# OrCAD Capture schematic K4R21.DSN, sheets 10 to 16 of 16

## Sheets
10 P11: Power, DDR3/VTT/VCore: size Custom; title: System Power supplies
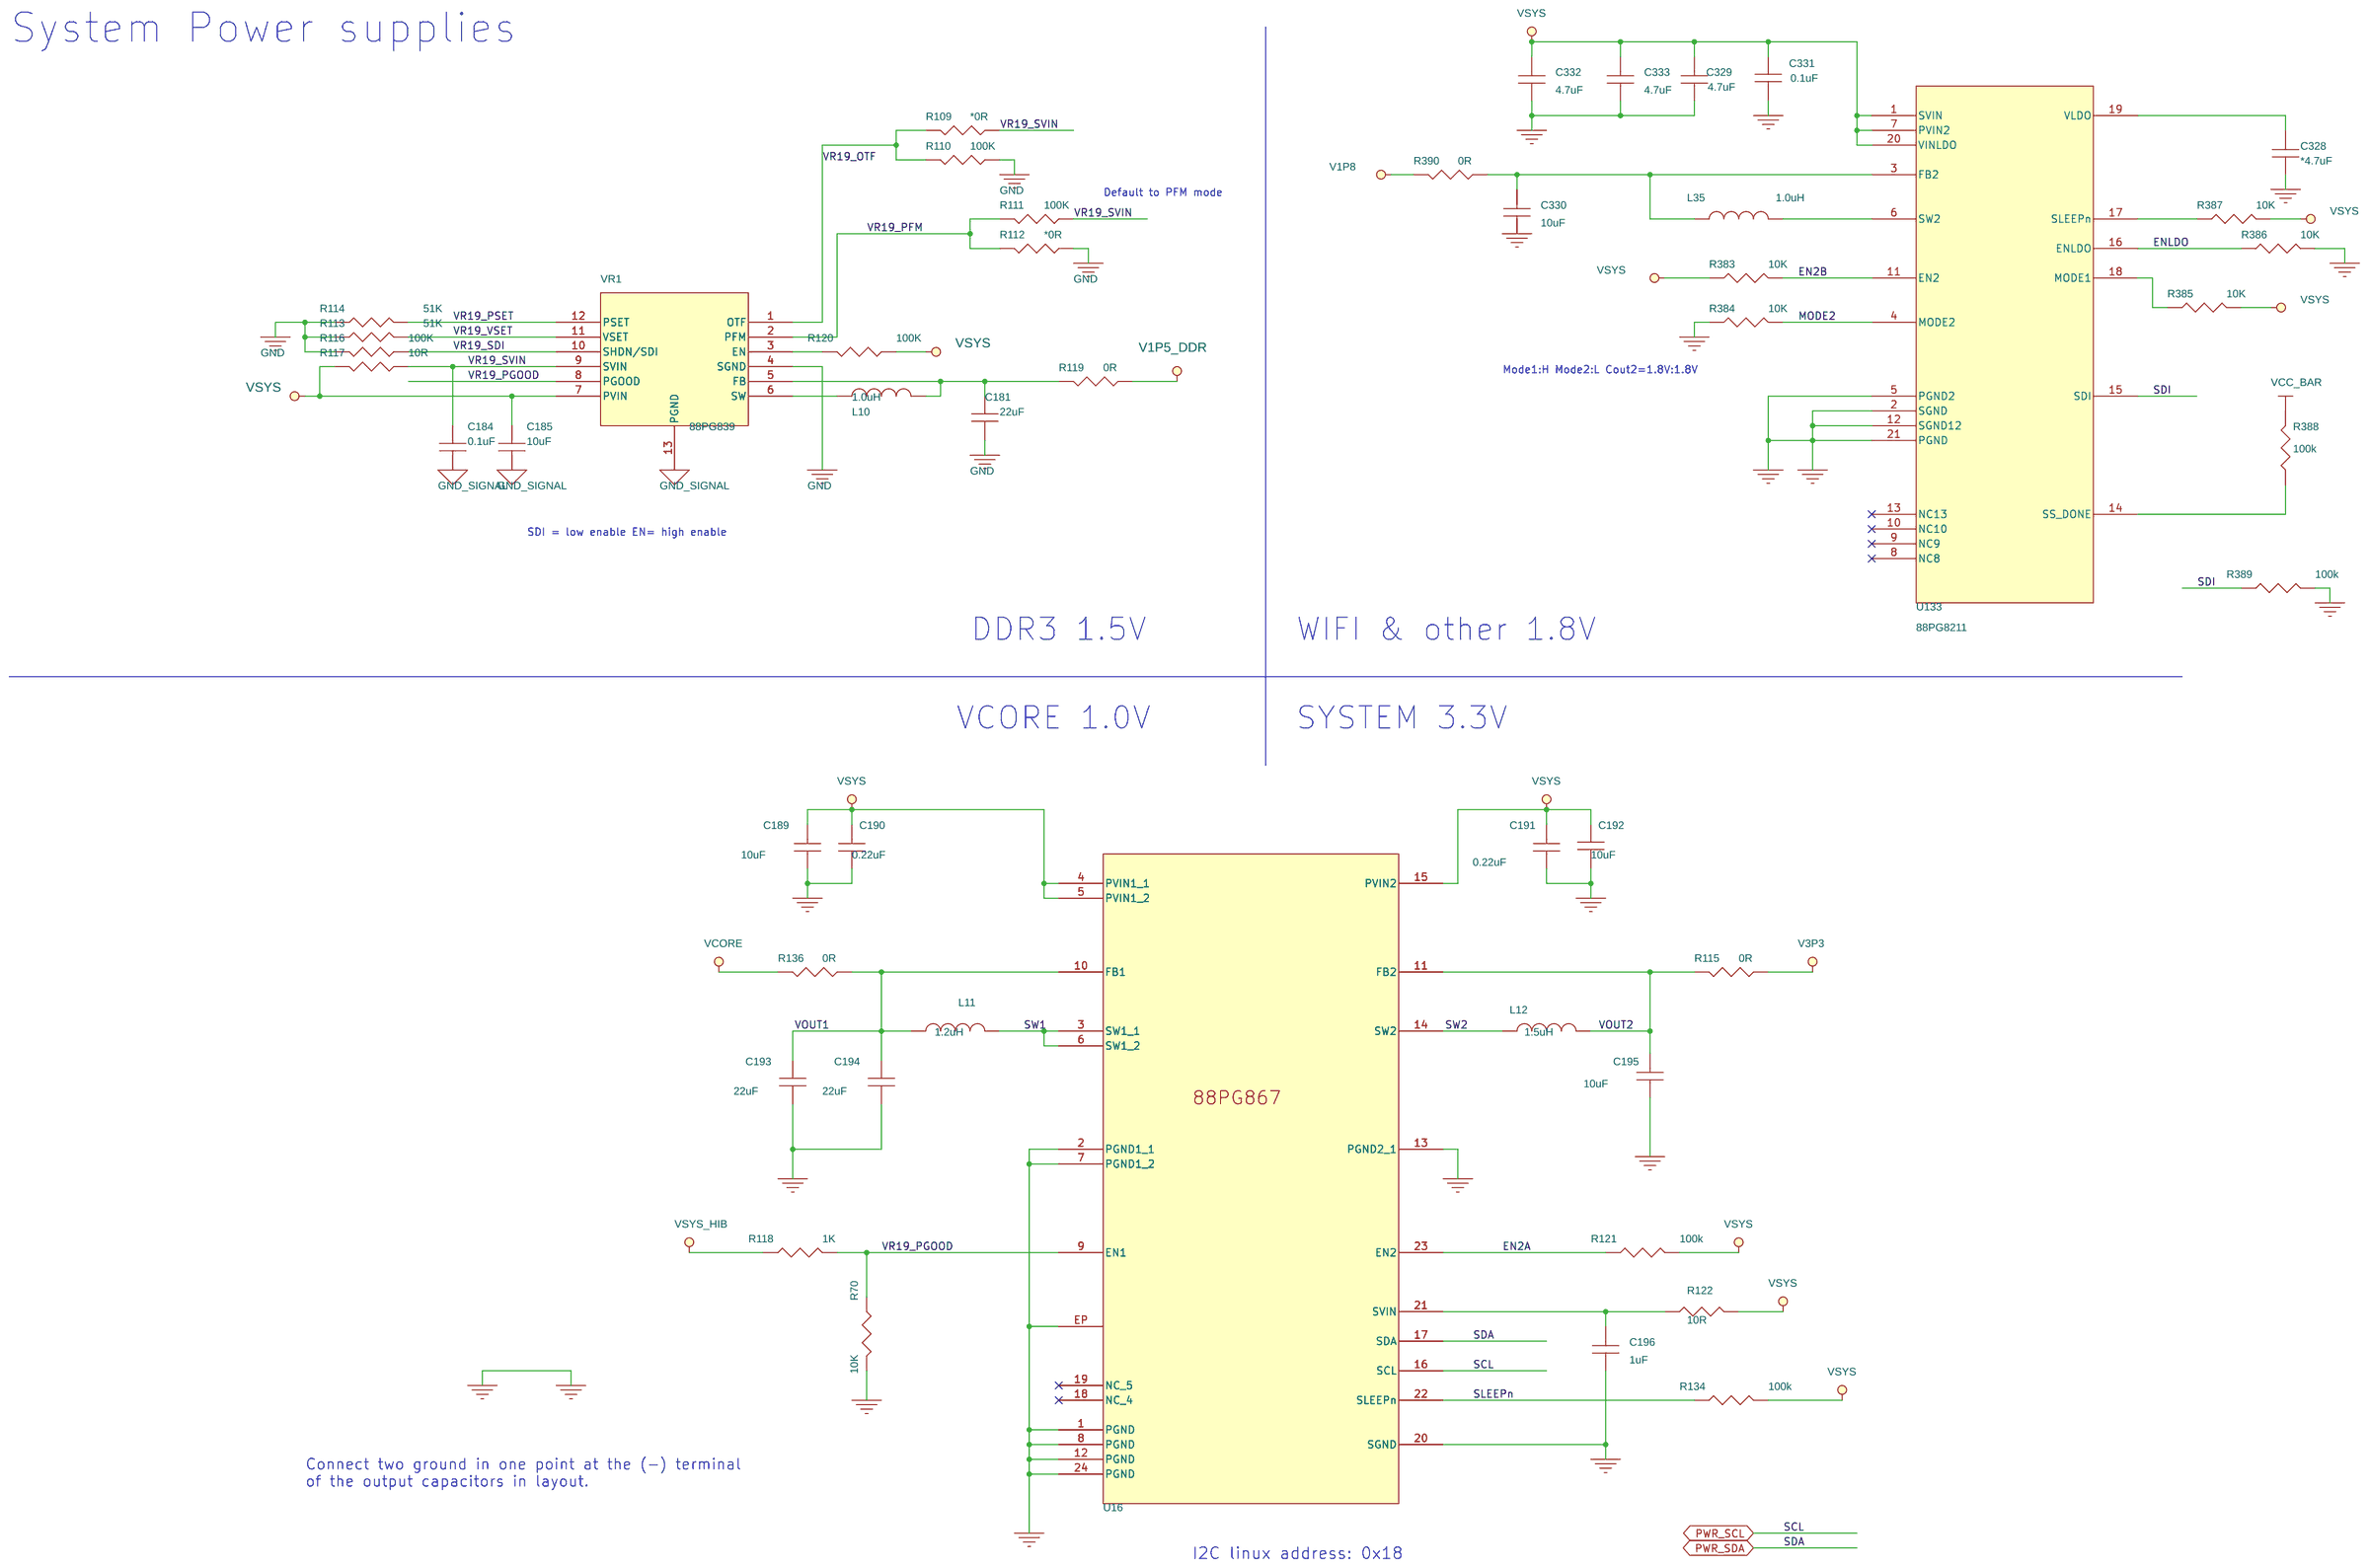
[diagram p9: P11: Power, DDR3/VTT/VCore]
11 P03: ASPEN-AUDIO/SDIO/MISC: size Custom; title: ASPEN-SPI/SDIO/etc
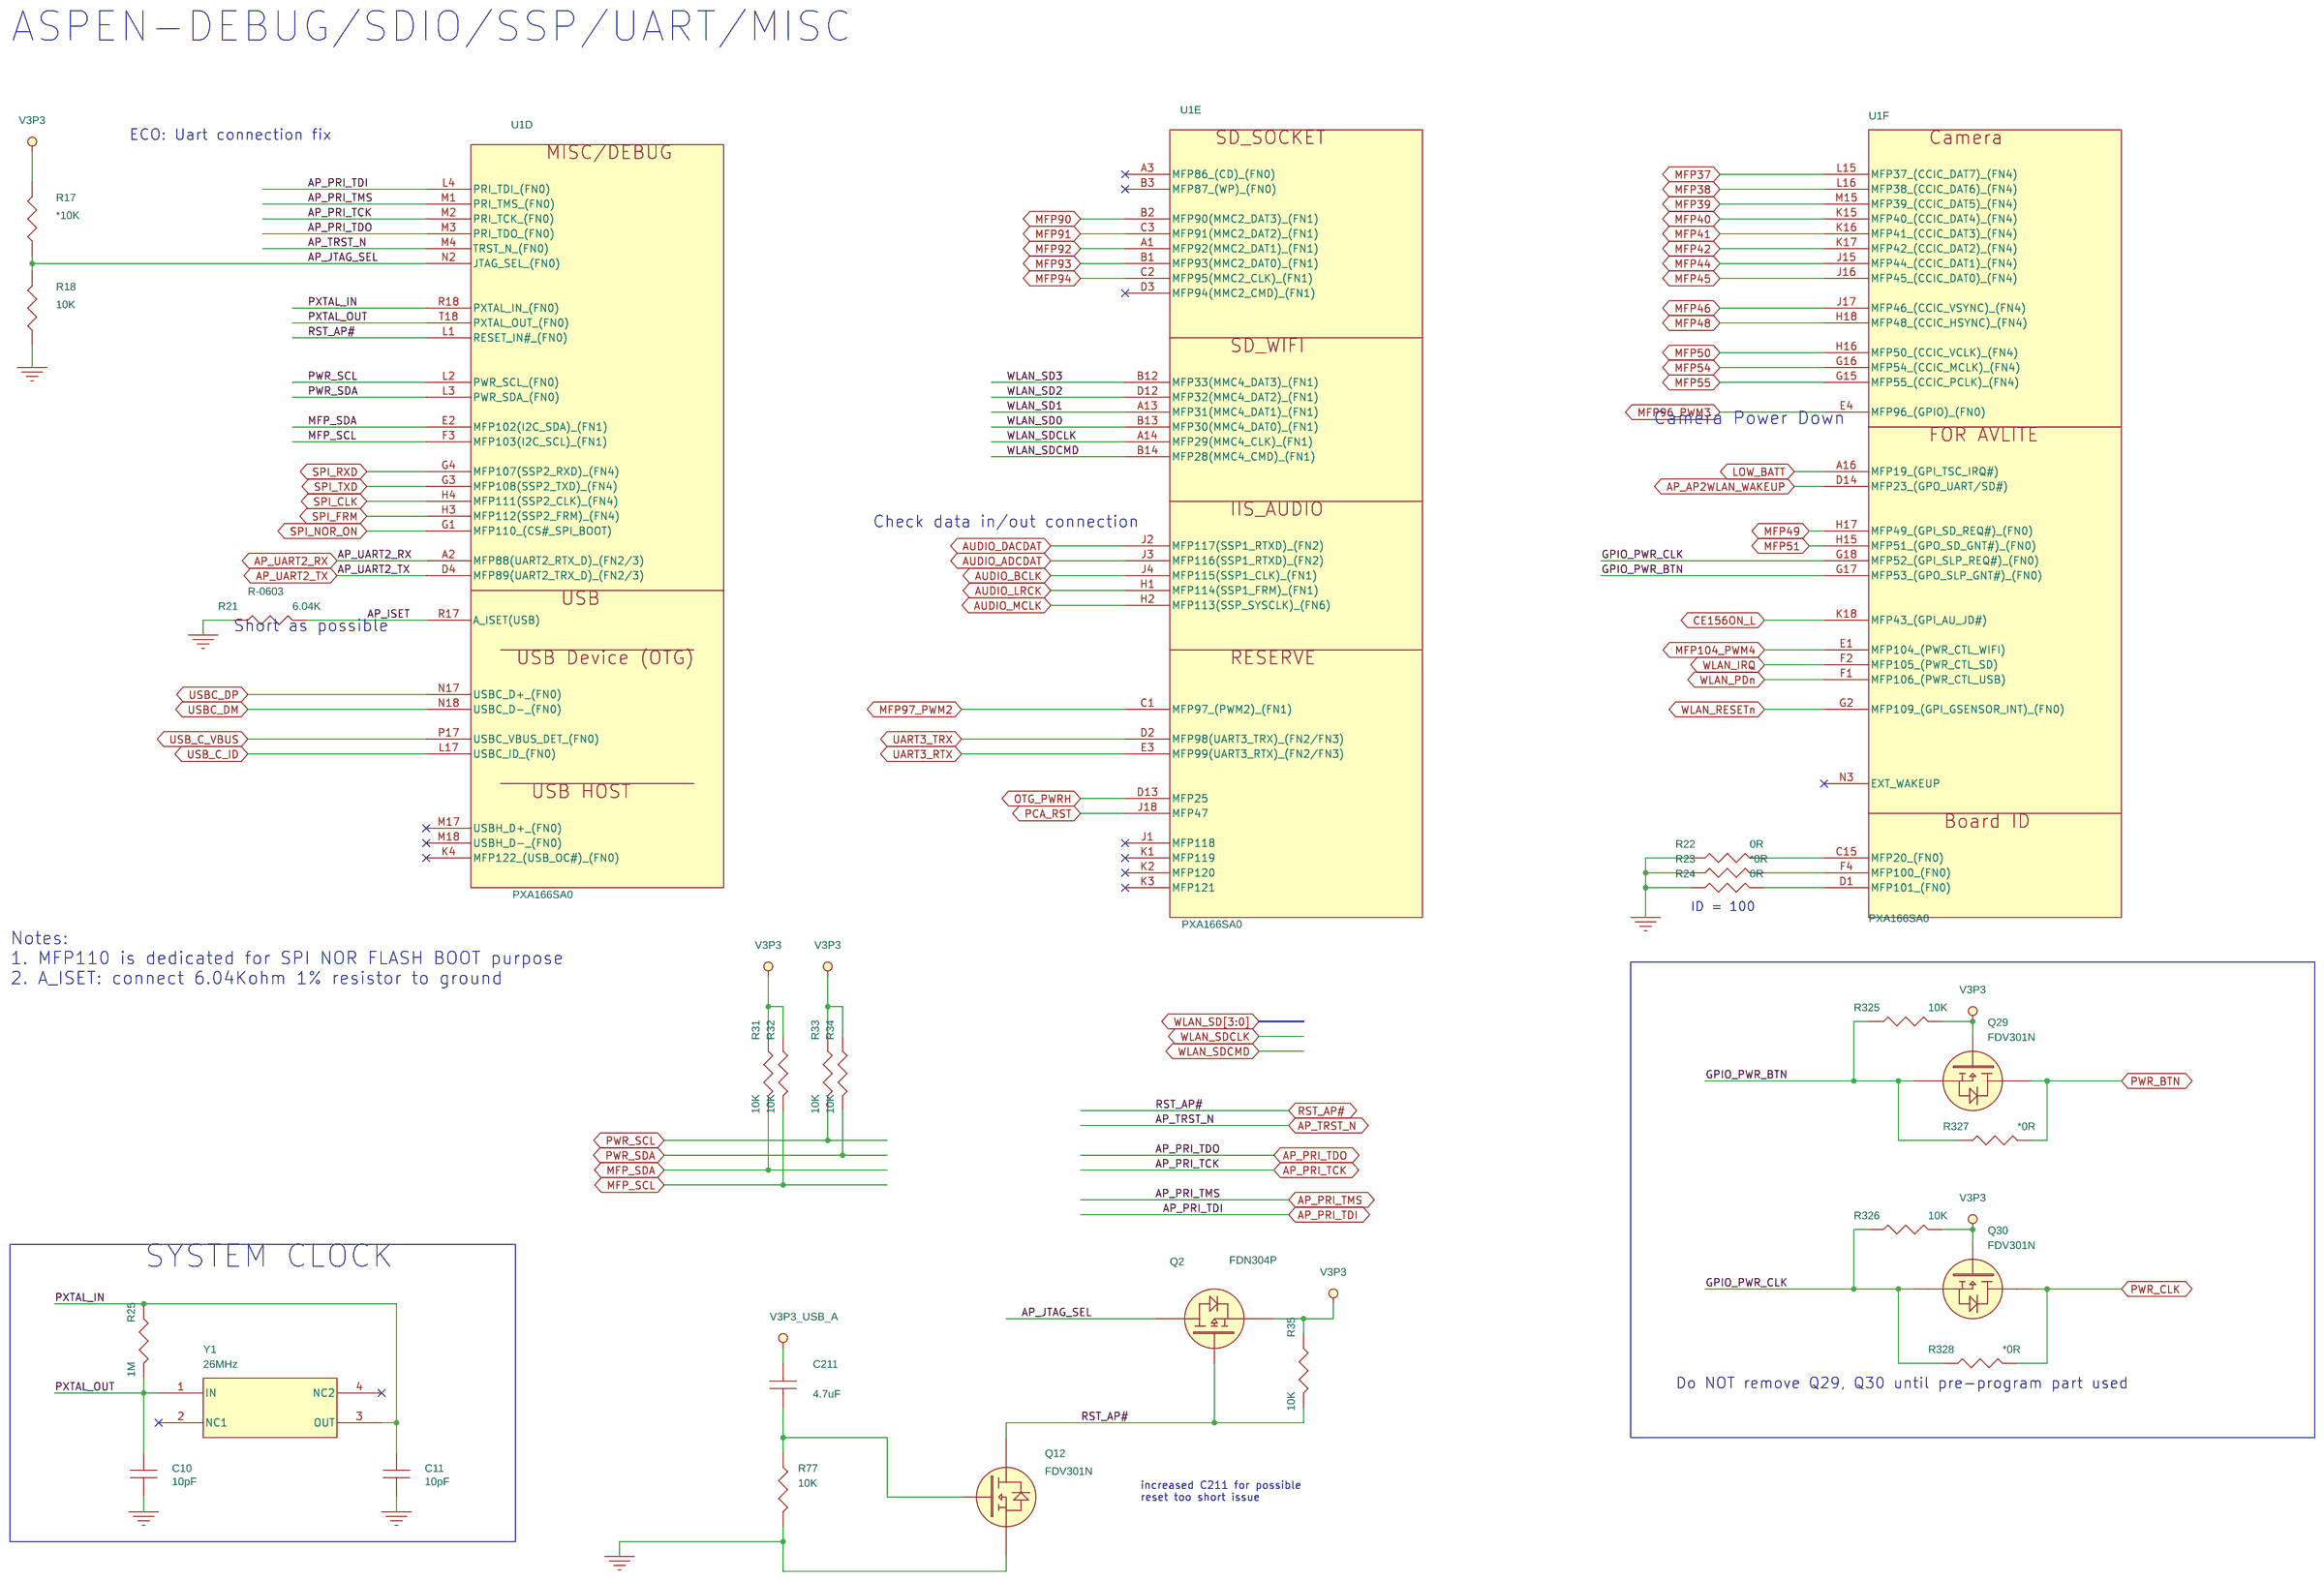
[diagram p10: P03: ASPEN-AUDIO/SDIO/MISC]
12 P10: Power Input and switch: size Custom; title: K4 Expansion
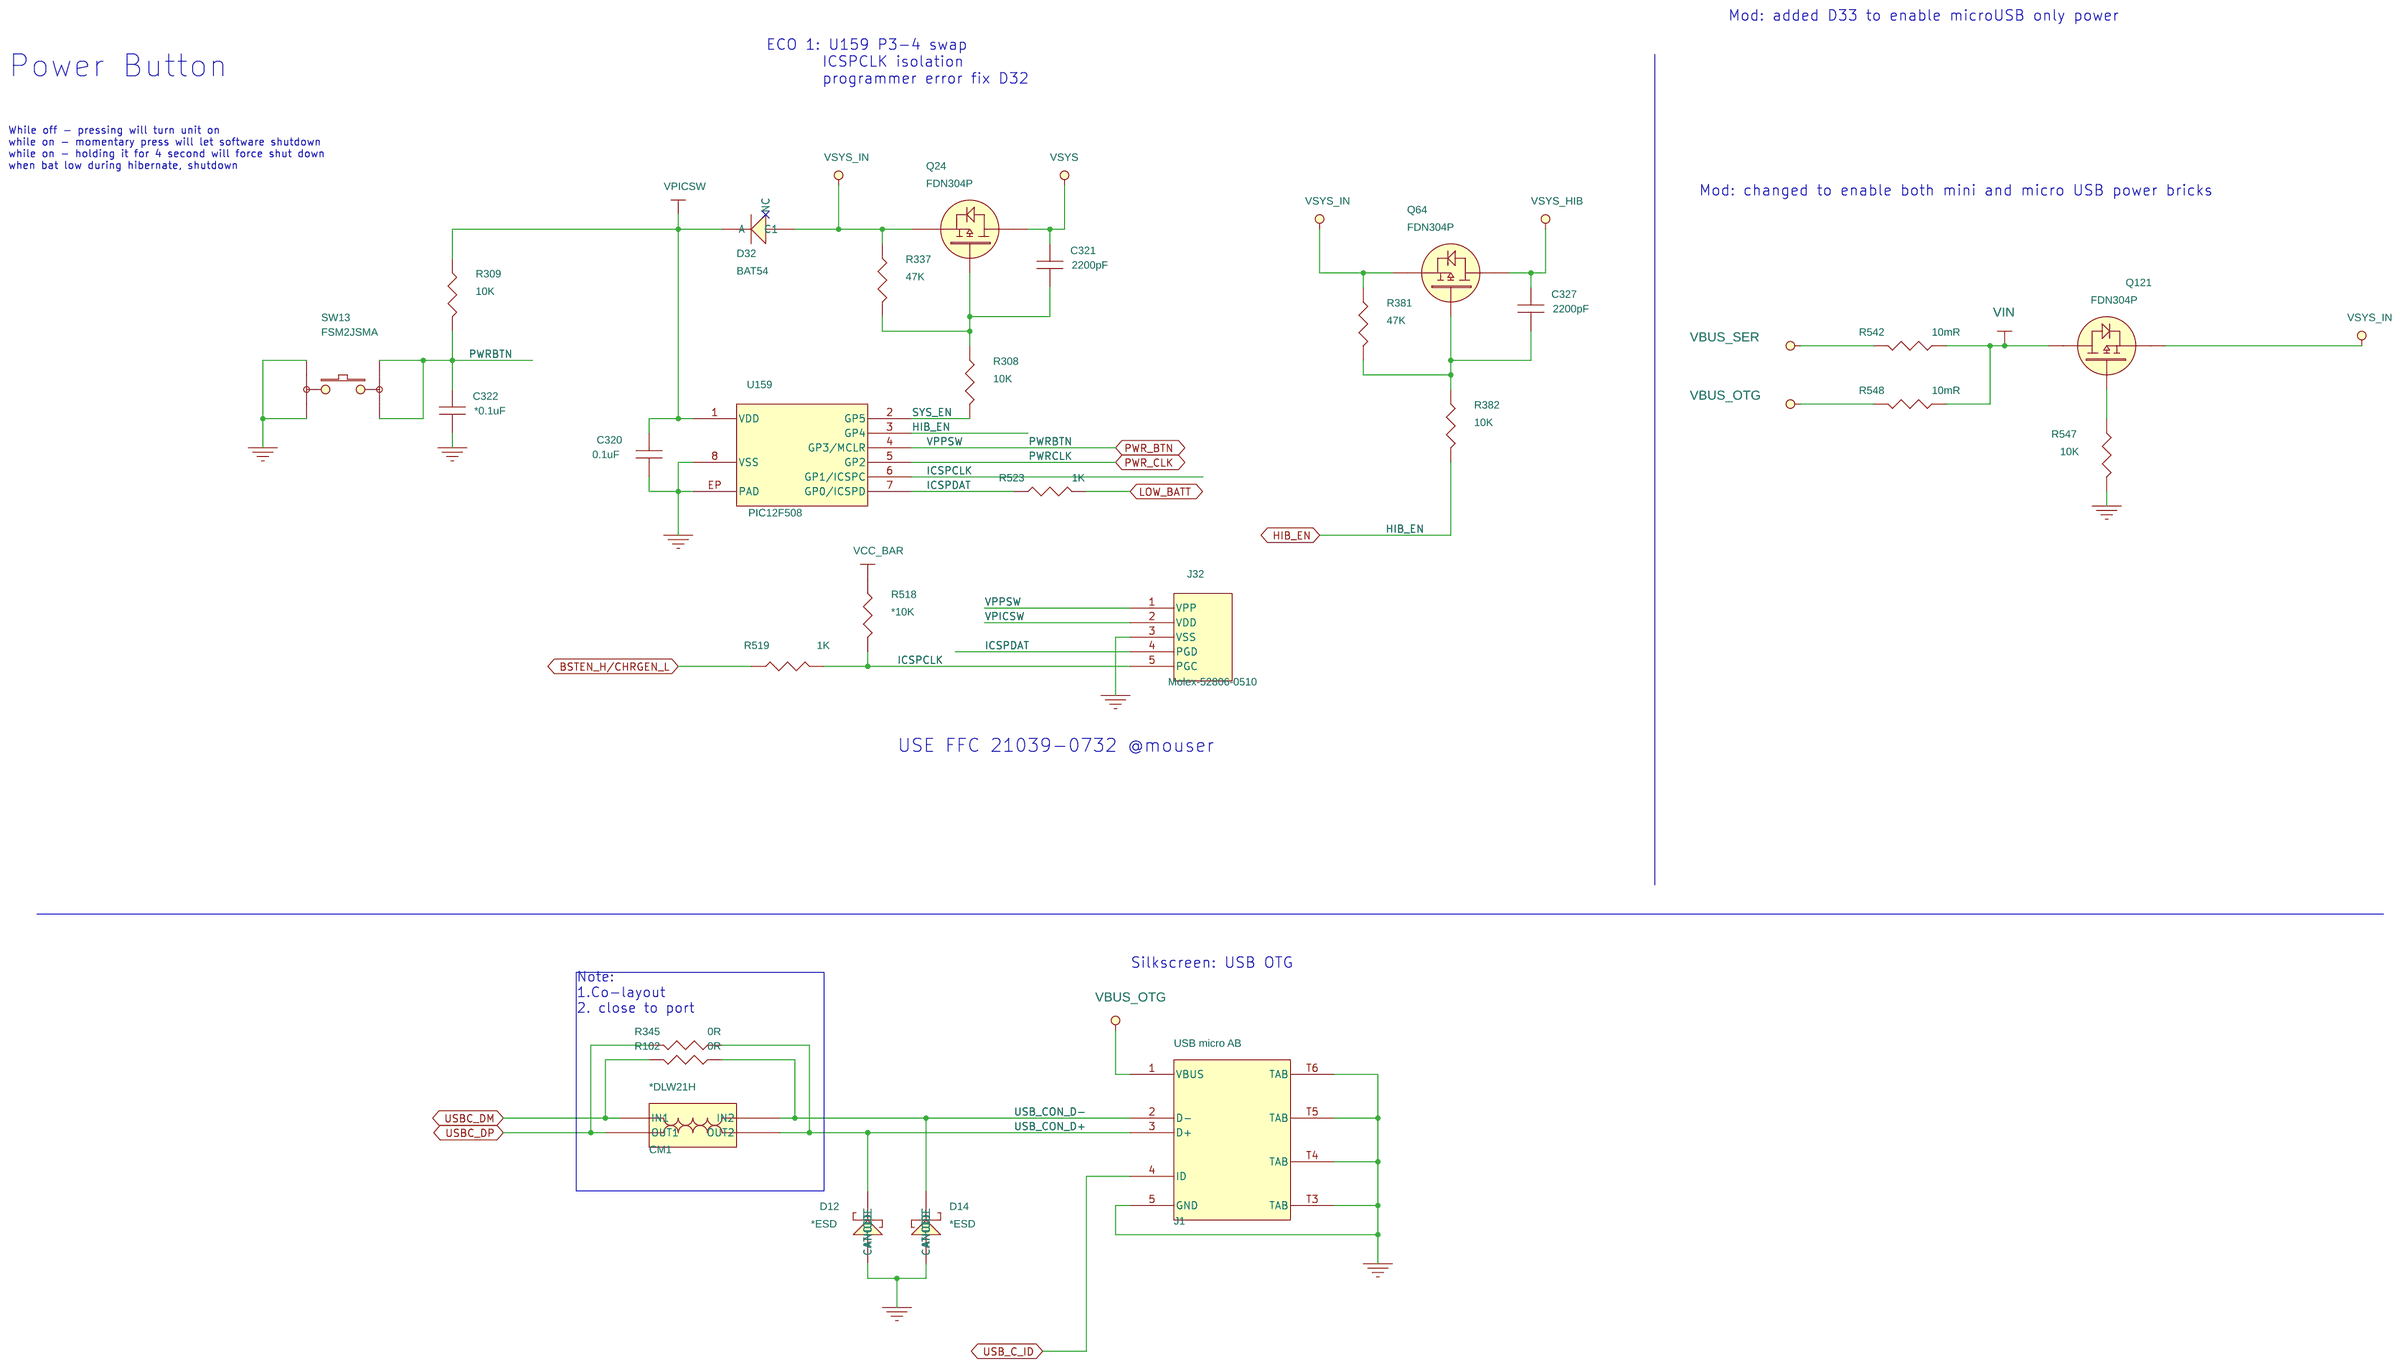
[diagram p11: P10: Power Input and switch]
13 P16: Back access 50 pin conn: size Custom; title: Bottom Expansion Connector
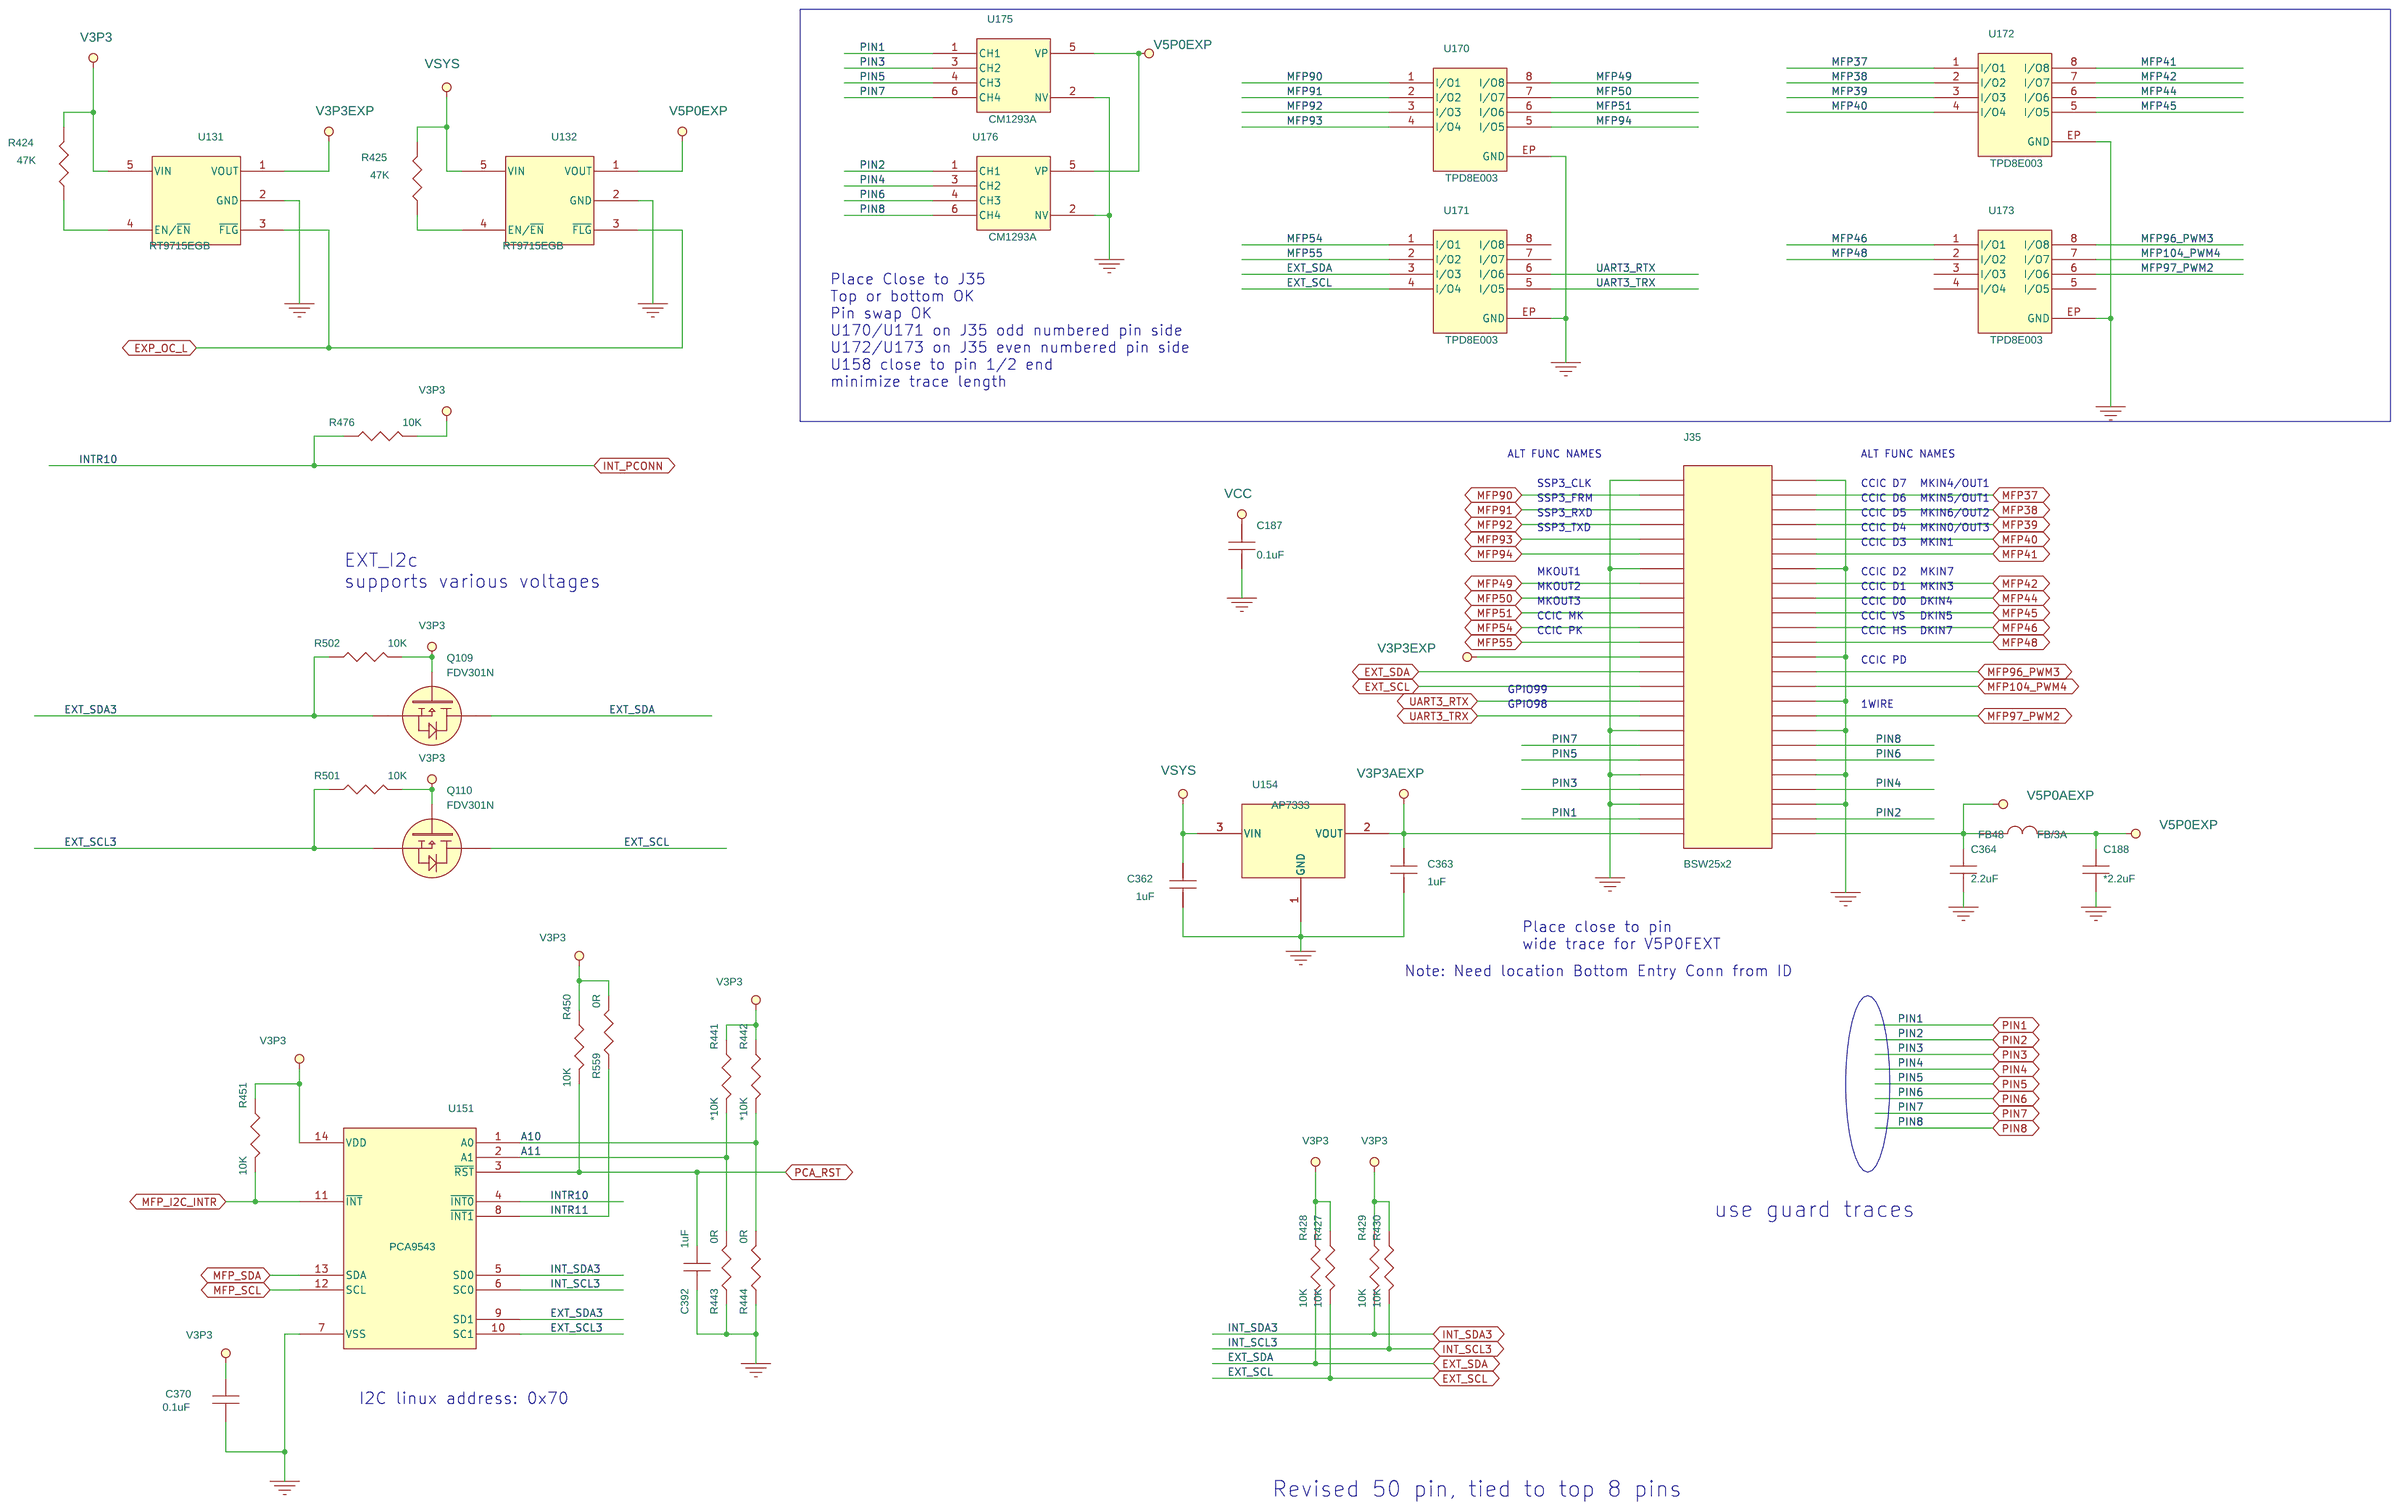
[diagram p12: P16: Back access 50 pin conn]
14 P13: Debug connectors + LEDs: size Custom; title: Debug/Console
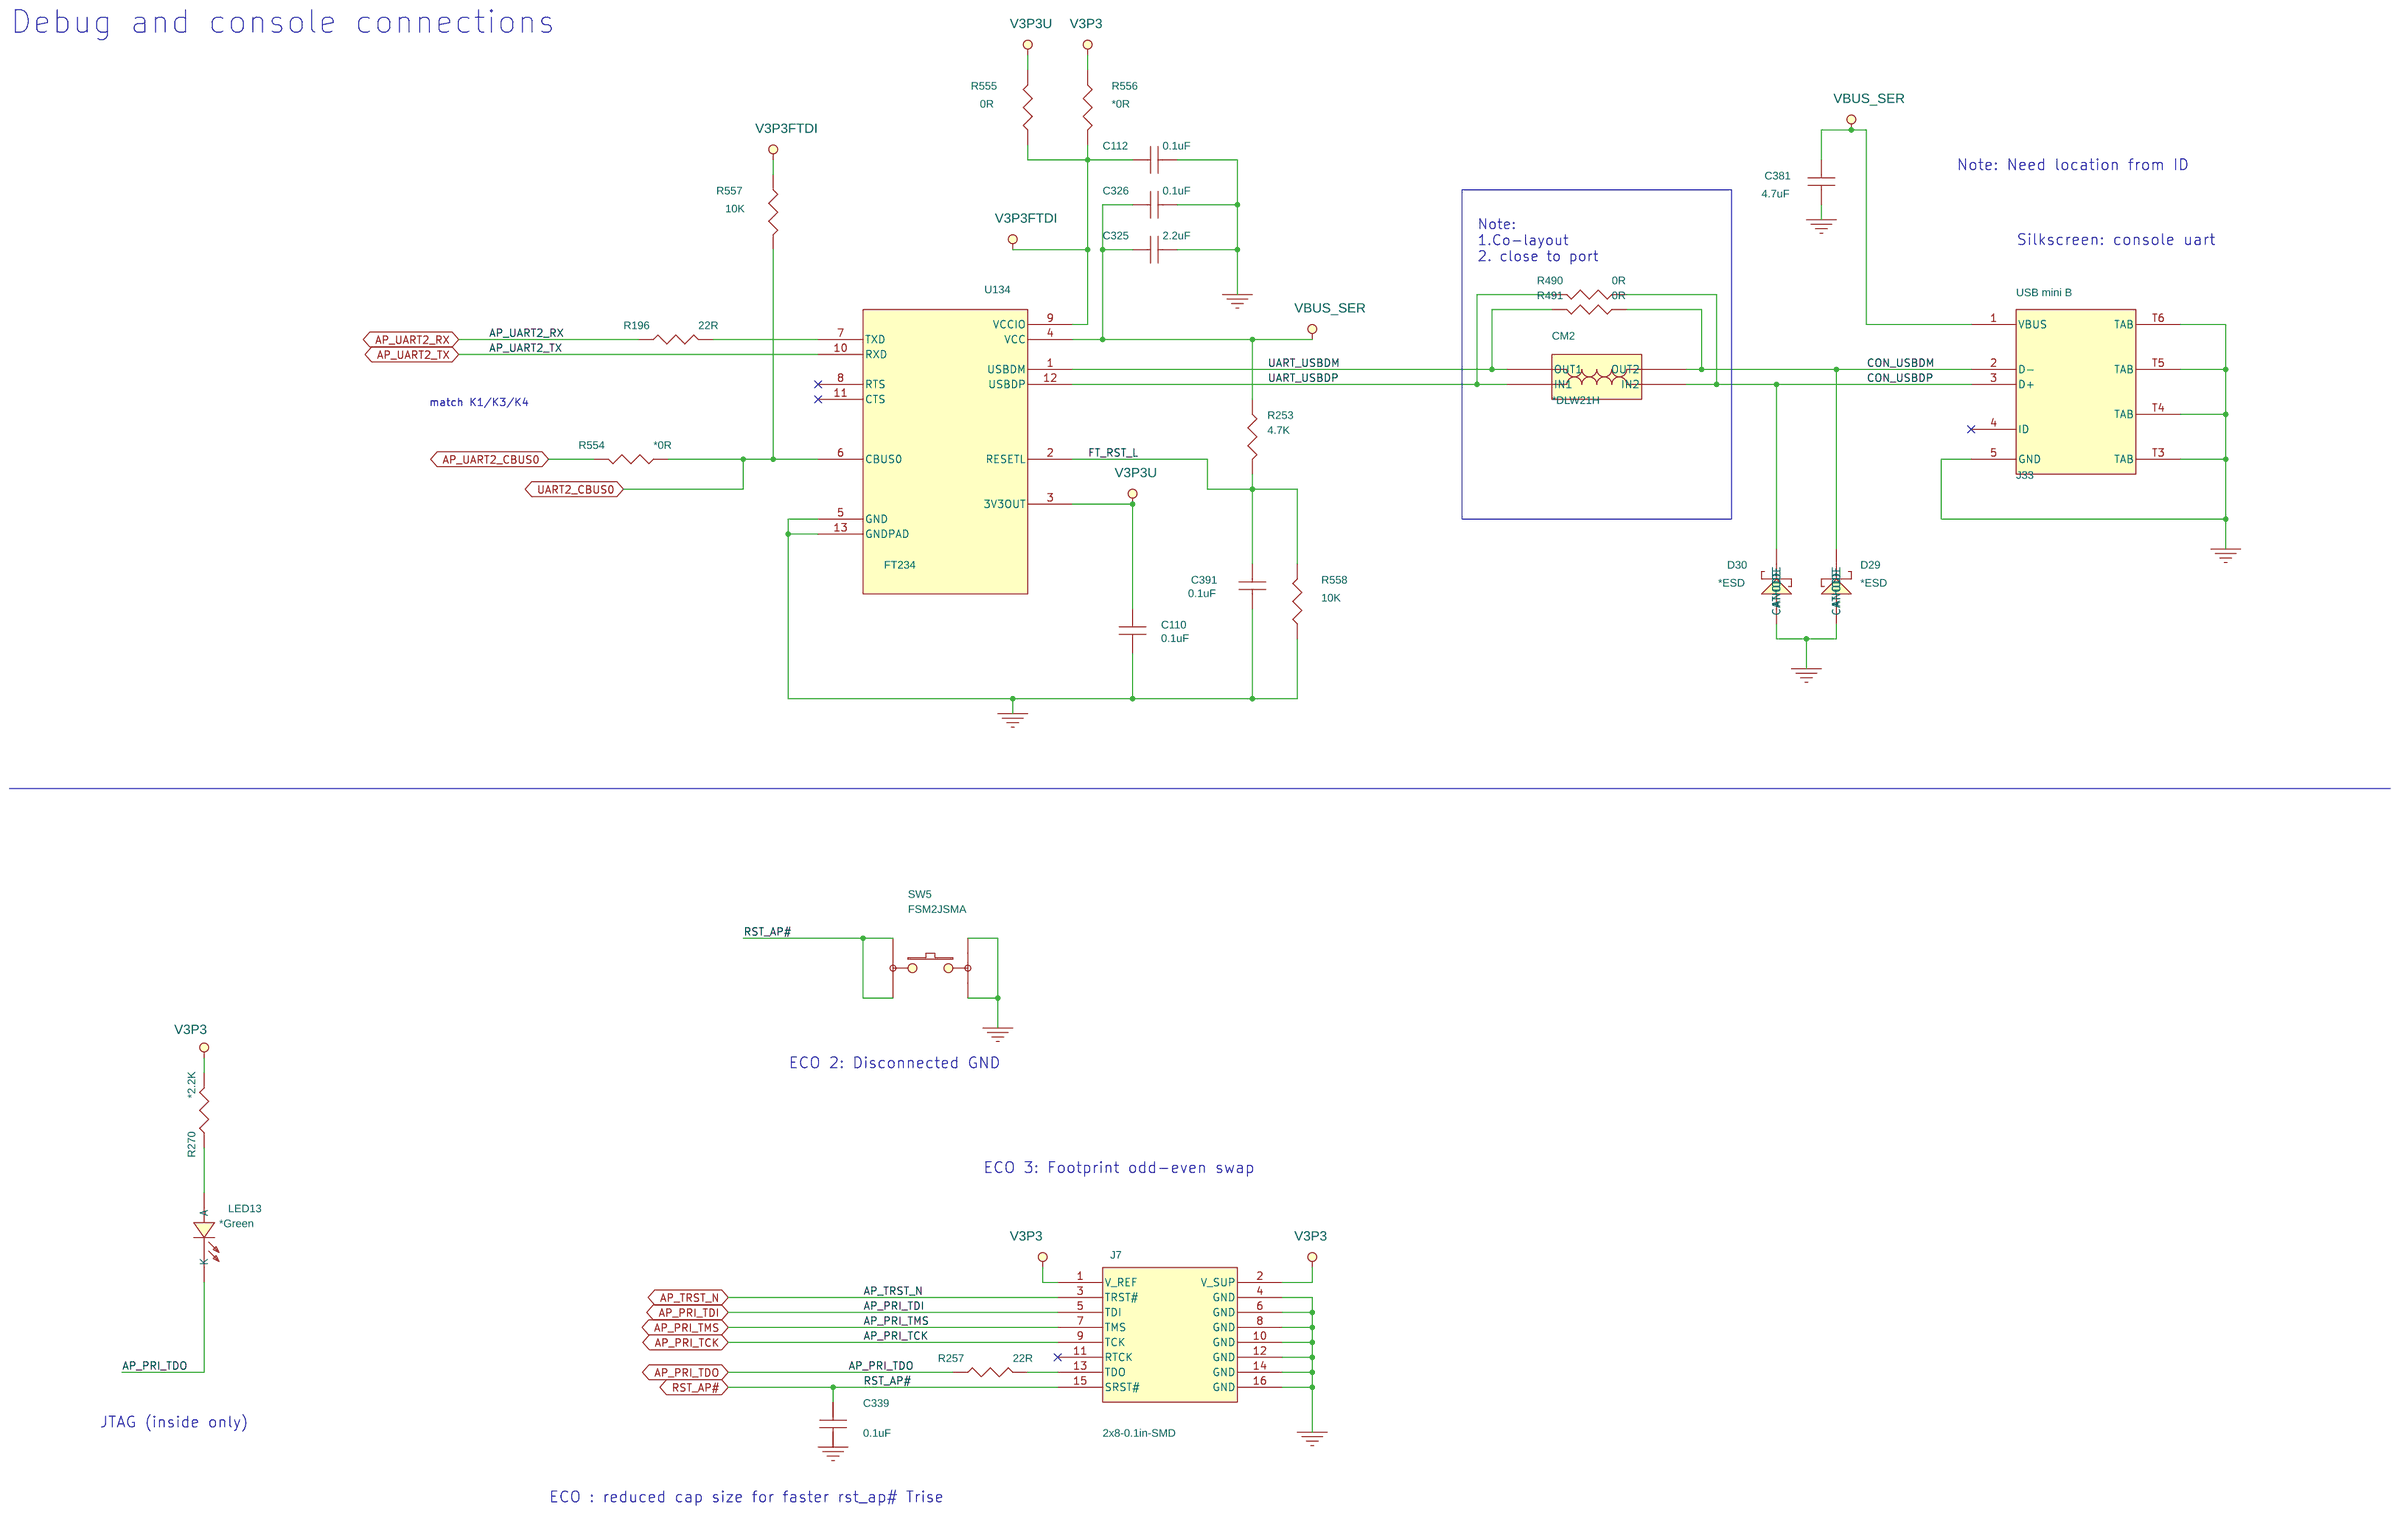
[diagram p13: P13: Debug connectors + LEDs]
15 P14: Front access 8 pin conn 1: size Custom; title: Programmable connectors
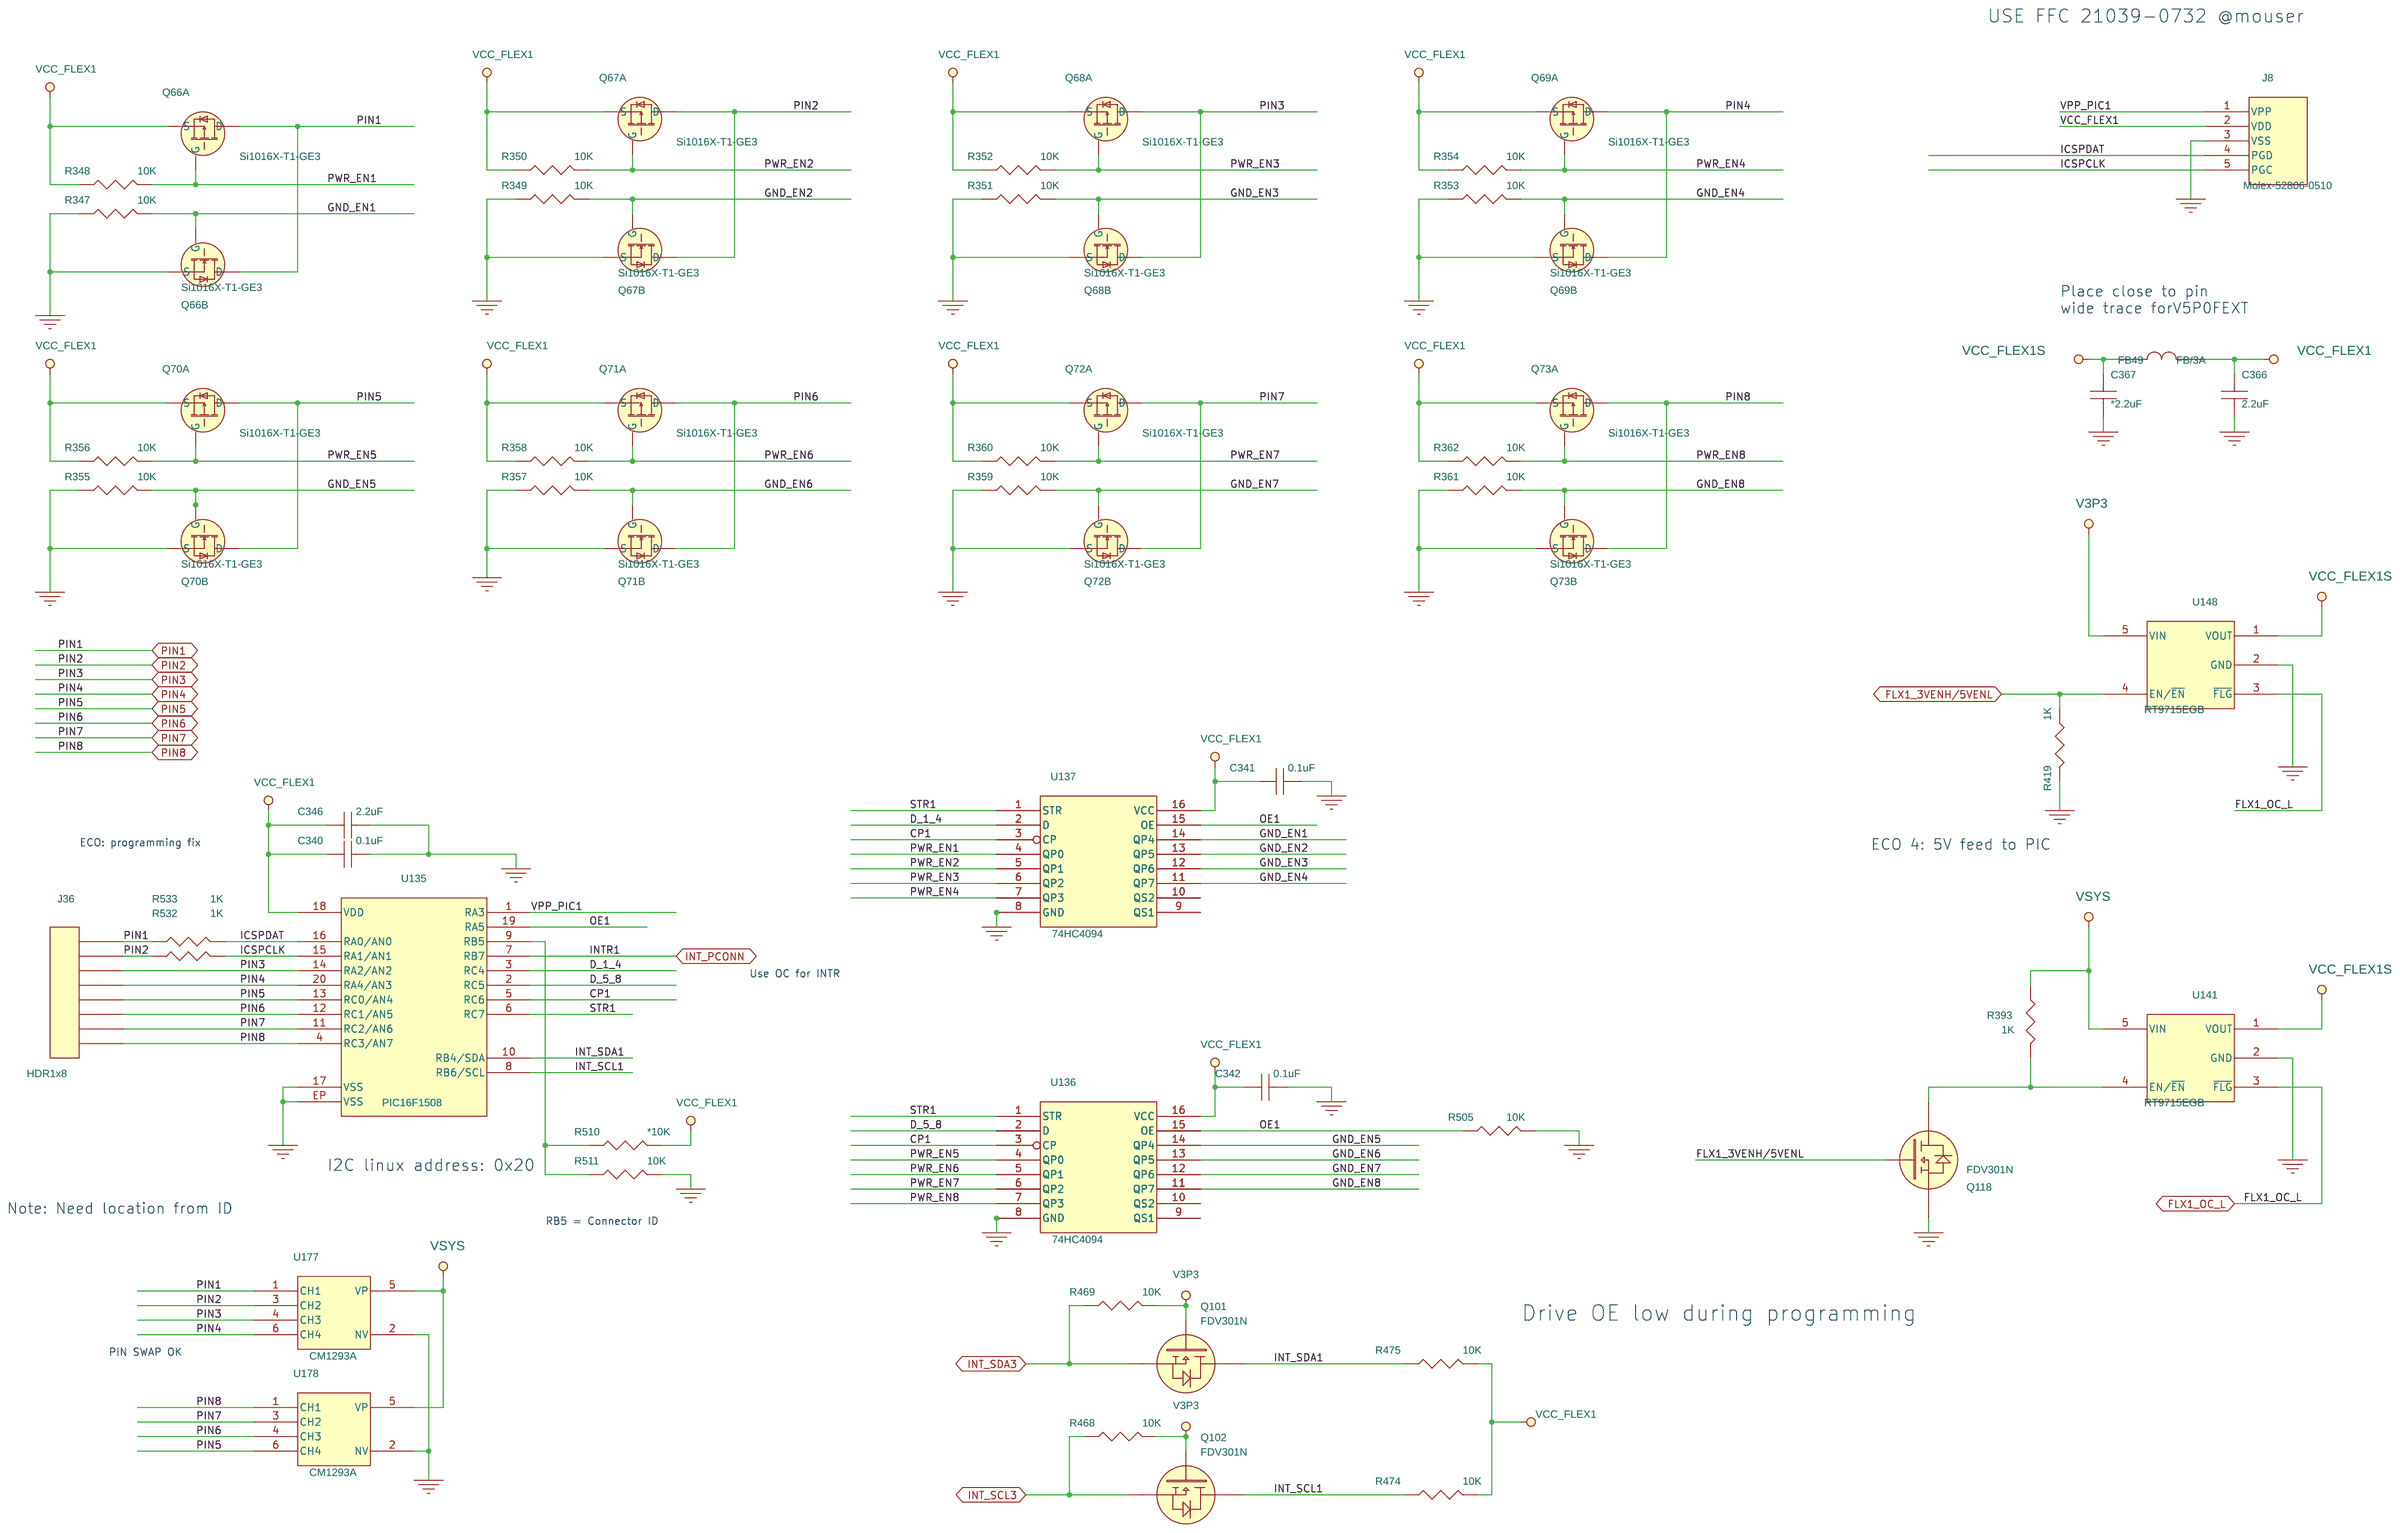
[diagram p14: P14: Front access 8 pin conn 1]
16 P15: Front access 8 pin conn 2: size Custom; title: Programmable connectors
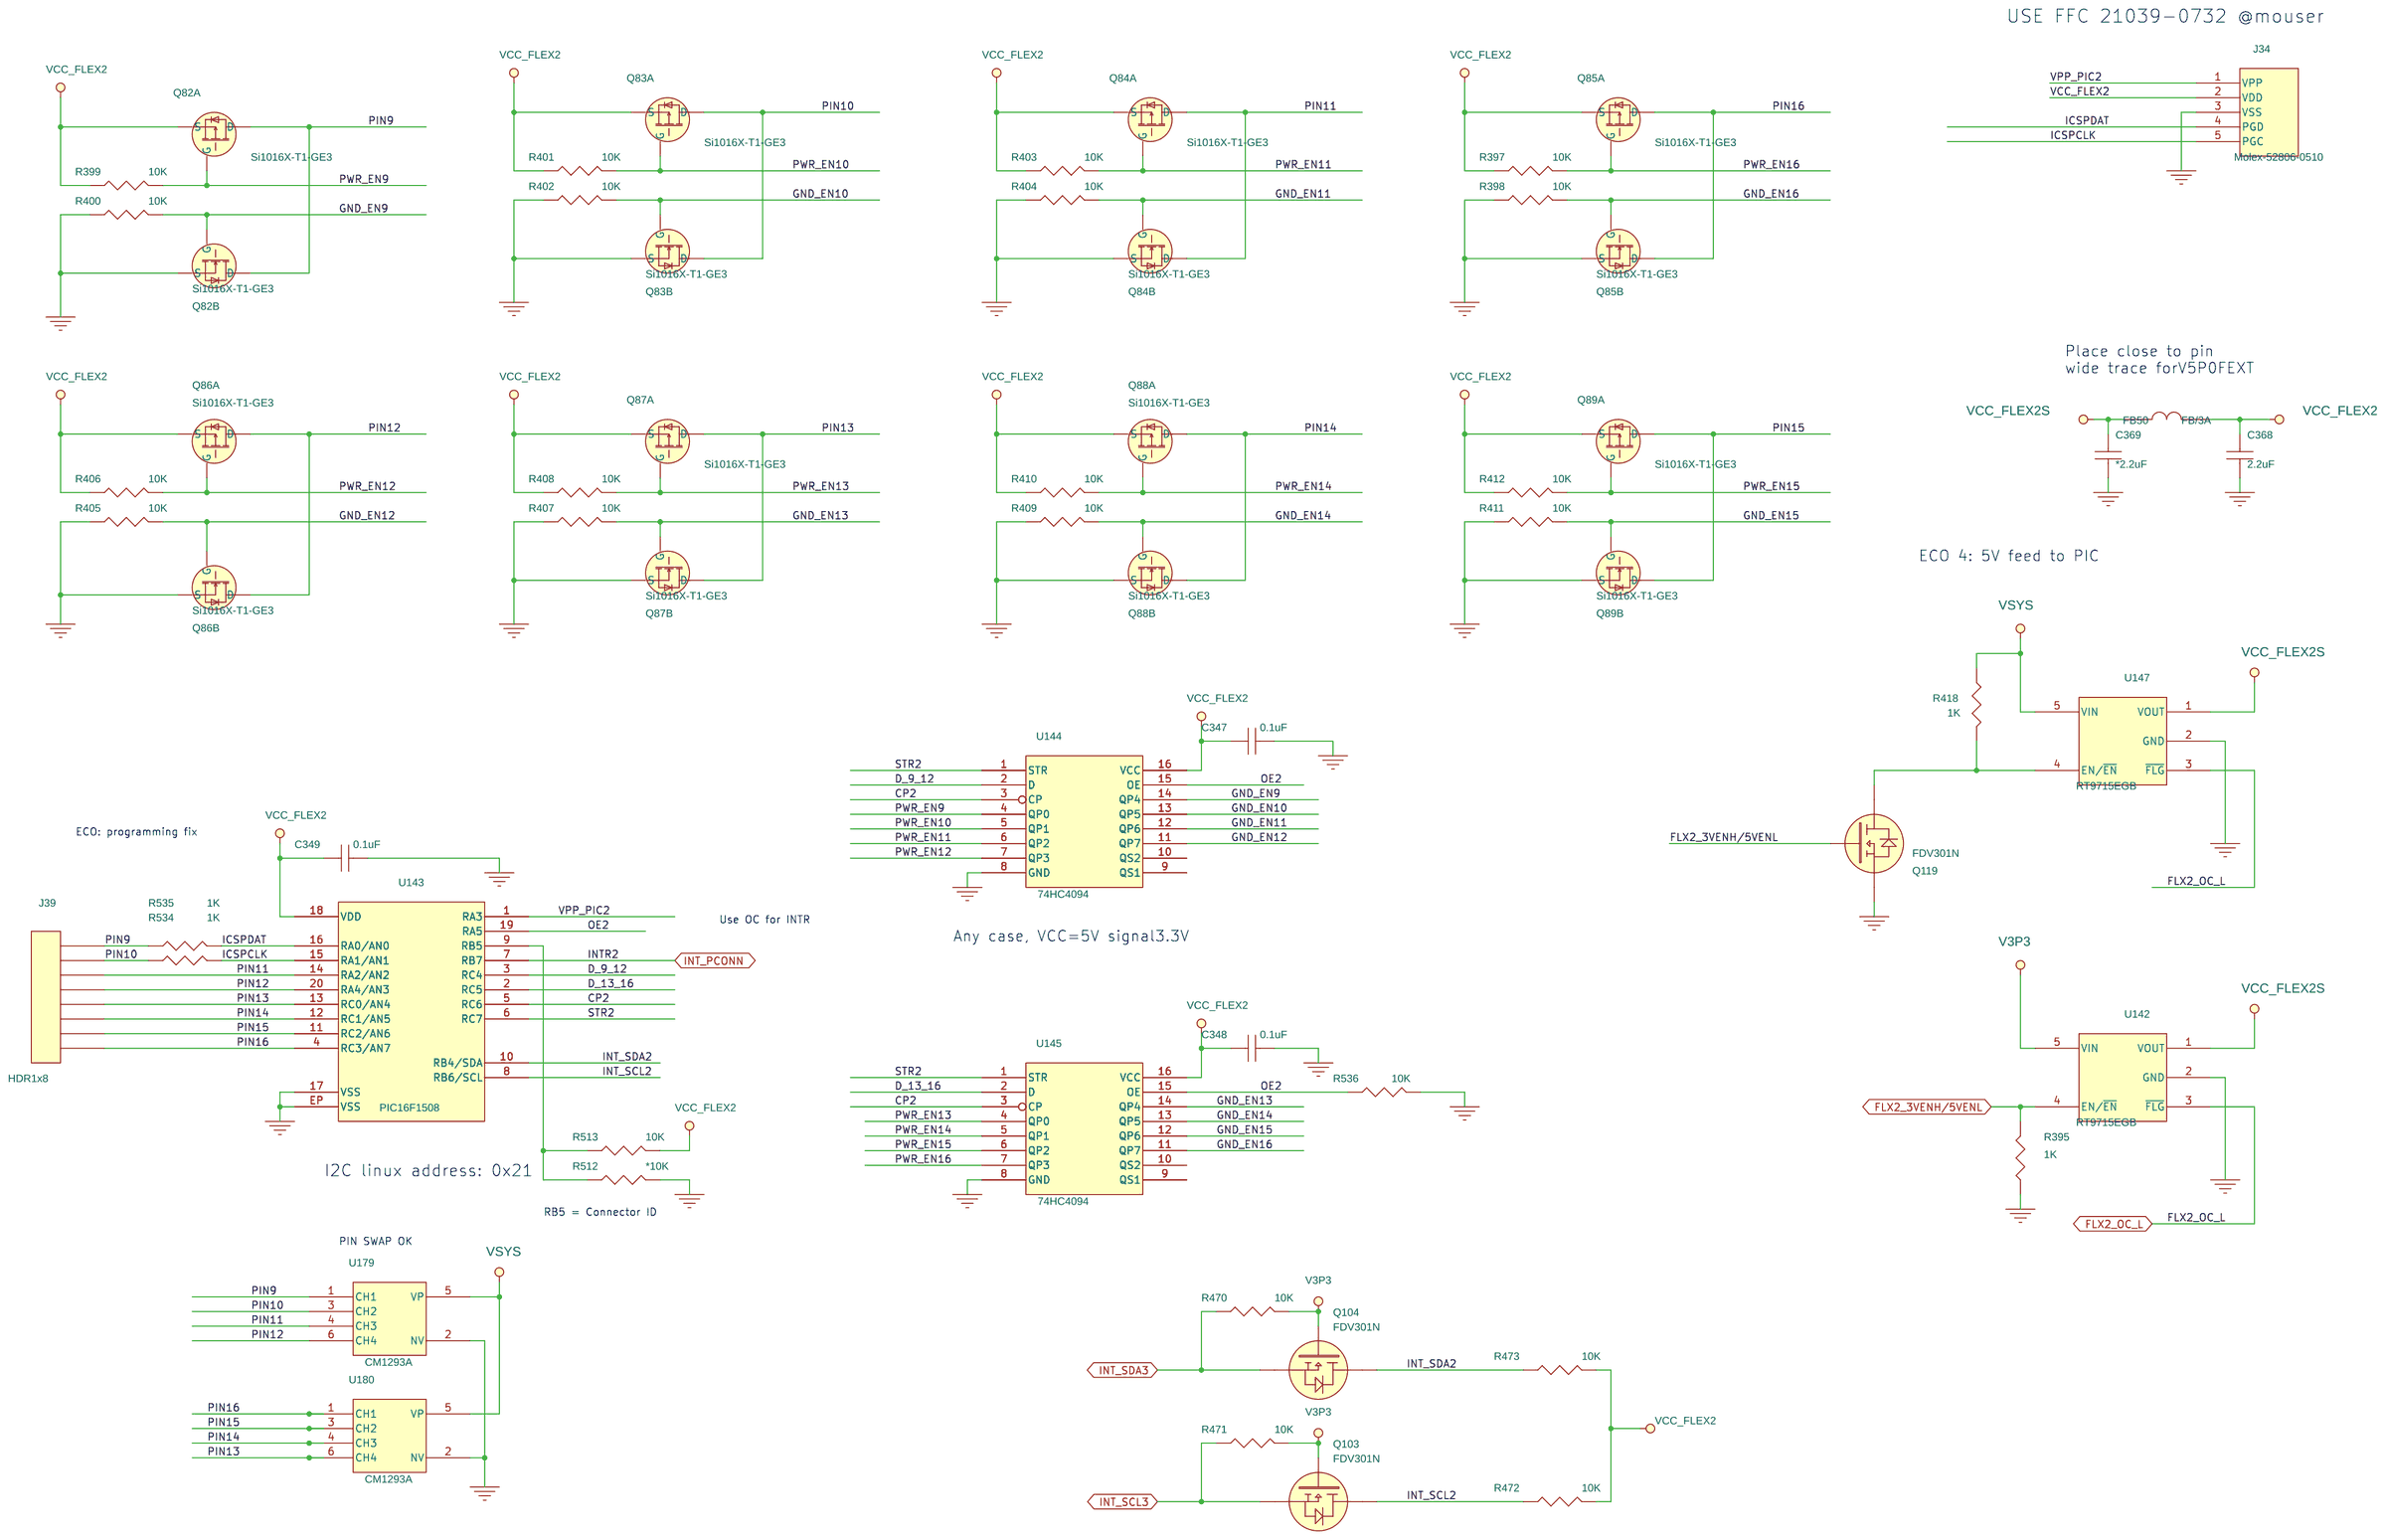
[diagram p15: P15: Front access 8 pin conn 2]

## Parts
sheet P02: ASPEN-MEM/USB/LCD
U1  PXA166SA0  [fbga-18x18-320]  (sections A,B,C,D,E,F)
sheet P03: ASPEN-AUDIO/SDIO/MISC
C10  10pF  [C-0402]
C11  10pF  [C-0402]
C211  4.7uF  [C-0402]
Q2  FDN304P  [SOT23-3]
Q12  FDV301N  [SOT-23a]
Q29  FDV301N  [SOT-23a]
Q30  FDV301N  [SOT-23a]
R17  *10K  [R-0402]
R18  10K  [R-0402]
R21  6.04K  [R-0603]
R22  0R  [R-0402]
R23  *0R  [R-0402]
R24  0R  [R-0402]
R25  1M  [R-0402]
R31  10K  [R-0402]
R32  10K  [R-0402]
R33  10K  [R-0402]
R34  10K  [R-0402]
R35  10K  [R-0402]
R77  10K  [R-0402]
R325  10K  [R-0402]
R326  10K  [R-0402]
R327  *0R  [R-0402]
R328  *0R  [R-0402]
Y1  26MHz  [o-3_2X2_5-4g]
sheet P10: Power Input and switch
C320  0.1uF  [C-0402]
C321  2200pF  [C-0402]
C322  *0.1uF  [C-0402]
C327  2200pF  [C-0402]
CM1  *DLW21H  [FIL-2X1_2-4]
D12  *ESD  [MicroSMP]
D14  *ESD  [MicroSMP]
D32  BAT54  [sot23]
J1  USB micro AB  [USB-MICRO-AB-HIROSE]
J32  Molex-52806-0510  [Molex_52806_0510]
Q24  FDN304P  [SOT23-3]
Q64  FDN304P  [SOT23-3]
Q121  FDN304P  [SOT23-3]
R102  0R  [R-0402]
R308  10K  [R-0402]
R309  10K  [R-0402]
R337  47K  [R-0402]
R345  0R  [R-0402]
R381  47K  [R-0402]
R382  10K  [R-0402]
R518  *10K  [R-0402]
R519  1K  [R-0402]
R523  1K  [R-0402]
R542  10mR  [R-0603]
R547  10K  [R-0402]
R548  10mR  [R-0603]
SW13  FSM2JSMA  [FSM2JSMATR]
U159  PIC12F508  [DFN8EP]
sheet P11: Power, DDR3/VTT/VCore
C181  22uF  [C-0603]
C184  0.1uF  [C-0402]
C185  10uF  [C-0603]
C189  10uF  [C-0603]
C190  0.22uF  [CAP_0201]
C191  0.22uF  [CAP_0201]
C192  10uF  [C-0603]
C193  22uF  [C-0603]
C194  22uF  [C-0603]
C195  10uF  [C-0402]
C196  1uF  [C0402]
C328  *4.7uF  [CAP_0603]
C329  4.7uF  [C-0603]
C330  10uF  [C-0402]
C331  0.1uF  [C-0402]
C332  4.7uF  [C-0603]
C333  4.7uF  [C-0603]
L10  1.0uH  [FLF3215]
L11  1.2uH  [VLC5020T]
L12  1.5uH  [INDUCTOR_MDT2520_CN_SERIES]
L35  1.0uH  [INDUCTOR_MDT2520_CR_SERIES]
R70  10K  [R-0402]
R109  *0R  [R-0402]
R110  100K  [R-0402]
R111  100K  [R-0402]
R112  *0R  [R-0402]
R113  51K  [R-0402]
R114  51K  [R-0402]
R115  0R  [R-0603]
R116  100K  [R-0402]
R117  10R  [R-0402]
R118  1K  [R-0402]
R119  0R  [R-0603]
R120  100K  [R-0402]
R121  100k  [R-0402]
R122  10R  [R-0402]
R134  100k  [R-0402]
R136  0R  [R-0603]
R383  10K  [R-0402]
R384  10K  [R-0402]
R385  10K  [R-0402]
R386  10K  [R-0402]
R387  10K  [R-0402]
R388  100k  [R-0402]
R389  100k  [R-0402]
R390  0R  [R-0603]
U16  88PG867  [3x4QFN24]
U133  88PG8211  [4X3QFN16_PAD_LENGTH_0P8MM_32MIL]
VR1  88PG839  [DFN-12]
sheet P13: Debug connectors + LEDs
C110  0.1uF  [C-0402]
C112  0.1uF  [C-0402]
C325  2.2uF  [C-0402]
C326  0.1uF  [C-0402]
C339  0.1uF  [C-0402]
C381  4.7uF  [C-0603]
C391  0.1uF  [C-0402]
CM2  *DLW21H  [FIL-2X1_2-4]
D29  *ESD  [MicroSMP]
D30  *ESD  [MicroSMP]
J7  2x8-0.1in-SMD  [SKT2x8_100MIL_SMD]
J33  USB mini B  [USB-MINI-B-MOLEX]
LED13  *Green  [LED-0603]
R196  22R  [R-0402]
R253  4.7K  [R-0402]
R257  22R  [R-0402]
R270  *2.2K  [R-0402]
R490  0R  [R-0402]
R491  0R  [R-0402]
R554  *0R  [R-0402]
R555  0R  [R-0402]
R556  *0R  [R-0402]
R557  10K  [R-0402]
R558  10K  [R-0402]
SW5  FSM2JSMA  [FSM2JSMATR]
U134  FT234  [DFN12]
sheet P14: Front access 8 pin conn 1
C340  0.1uF  [C-0402]
C341  0.1uF  [C-0402]
C342  0.1uF  [C-0402]
C346  2.2uF  [C-0402]
C366  2.2uF  [C-0402]
C367  *2.2uF  [C-0402]
FB49  FB/3A  [L-0603]
J8  Molex-52806-0510  [Molex_52806_0510]
J36  HDR1x8  [HDR1x8_100milSMT]
Q66  Si1016X-T1-GE3  [SOT-563]  (sections A,B)
Q67  Si1016X-T1-GE3  [SOT-563]  (sections A,B)
Q68  Si1016X-T1-GE3  [SOT-563]  (sections A,B)
Q69  Si1016X-T1-GE3  [SOT-563]  (sections A,B)
Q70  Si1016X-T1-GE3  [SOT-563]  (sections A,B)
Q71  Si1016X-T1-GE3  [SOT-563]  (sections A,B)
Q72  Si1016X-T1-GE3  [SOT-563]  (sections A,B)
Q73  Si1016X-T1-GE3  [SOT-563]  (sections A,B)
Q101  FDV301N  [SOT-23a]
Q102  FDV301N  [SOT-23a]
Q118  FDV301N  [SOT-23a]
R347  10K  [R-0201]
R348  10K  [R-0201]
R349  10K  [R-0201]
R350  10K  [R-0201]
R351  10K  [R-0201]
R352  10K  [R-0201]
R353  10K  [R-0201]
R354  10K  [R-0201]
R355  10K  [R-0201]
R356  10K  [R-0201]
R357  10K  [R-0201]
R358  10K  [R-0201]
R359  10K  [R-0201]
R360  10K  [R-0201]
R361  10K  [R-0201]
R362  10K  [R-0201]
R393  1K  [R-0402]
R419  1K  [R-0402]
R468  10K  [R-0201]
R469  10K  [R-0201]
R474  10K  [R-0201]
R475  10K  [R-0201]
R505  10K  [R-0201]
R510  *10K  [R-0201]
R511  10K  [R-0201]
R532  1K  [R-0402]
R533  1K  [R-0402]
U135  PIC16F1508  [QFN20]
U136  74HC4094  [TSSOP16]
U137  74HC4094  [TSSOP16]
U141  RT9715EGB  [SOT23-5]
U148  RT9715EGB  [SOT23-5]
U177  CM1293A  [SC-74]
U178  CM1293A  [SC-74]
sheet P15: Front access 8 pin conn 2
C347  0.1uF  [C-0402]
C348  0.1uF  [C-0402]
C349  0.1uF  [C-0402]
C368  2.2uF  [C-0402]
C369  *2.2uF  [C-0402]
FB50  FB/3A  [L-0603]
J34  Molex-52806-0510  [Molex_52806_0510]
J39  HDR1x8  [HDR1x8_100milSMT]
Q82  Si1016X-T1-GE3  [SOT-563]  (sections A,B)
Q83  Si1016X-T1-GE3  [SOT-563]  (sections A,B)
Q84  Si1016X-T1-GE3  [SOT-563]  (sections A,B)
Q85  Si1016X-T1-GE3  [SOT-563]  (sections A,B)
Q86  Si1016X-T1-GE3  [SOT-563]  (sections A,B)
Q87  Si1016X-T1-GE3  [SOT-563]  (sections A,B)
Q88  Si1016X-T1-GE3  [SOT-563]  (sections A,B)
Q89  Si1016X-T1-GE3  [SOT-563]  (sections A,B)
Q103  FDV301N  [SOT-23a]
Q104  FDV301N  [SOT-23a]
Q119  FDV301N  [SOT-23a]
R395  1K  [R-0402]
R397  10K  [R-0201]
R398  10K  [R-0201]
R399  10K  [R-0201]
R400  10K  [R-0201]
R401  10K  [R-0201]
R402  10K  [R-0201]
R403  10K  [R-0201]
R404  10K  [R-0201]
R405  10K  [R-0201]
R406  10K  [R-0201]
R407  10K  [R-0201]
R408  10K  [R-0201]
R409  10K  [R-0201]
R410  10K  [R-0201]
R411  10K  [R-0201]
R412  10K  [R-0201]
R418  1K  [R-0402]
R470  10K  [R-0201]
R471  10K  [R-0201]
R472  10K  [R-0201]
R473  10K  [R-0201]
R512  *10K  [R-0201]
R513  10K  [R-0201]
R534  1K  [R-0402]
R535  1K  [R-0402]
R536  10K  [R-0201]
U142  RT9715EGB  [SOT23-5]
U143  PIC16F1508  [QFN20]
U144  74HC4094  [TSSOP16]
U145  74HC4094  [TSSOP16]
U147  RT9715EGB  [SOT23-5]
U179  CM1293A  [SC-74]
U180  CM1293A  [SC-74]
sheet P16: Back access 50 pin conn
C187  0.1uF  [C-0402]
C188  *2.2uF  [C-0402]
C362  1uF  [C0402]
C363  1uF  [C0402]
C364  2.2uF  [C-0402]
C370  0.1uF  [C-0402]
C392  1uF  [C0402]
FB48  FB/3A  [L-0603]
J35  BSW25x2  [RCPT25x2_100mil_BOT]
Q109  FDV301N  [SOT-23a]
Q110  FDV301N  [SOT-23a]
R424  47K  [R-0402]
R425  47K  [R-0402]
R427  10K  [R-0402]
R428  10K  [R-0402]
R429  10K  [R-0402]
R430  10K  [R-0402]
R441  *10K  [R-0402]
R442  *10K  [R-0402]
R443  0R  [R-0402]
R444  0R  [R-0402]
R450  10K  [R-0402]
R451  10K  [R-0402]
R476  10K  [R-0402]
R501  10K  [R-0402]
R502  10K  [R-0402]
R559  0R  [R-0402]
U131  RT9715EGB  [SOT23-5]
U132  RT9715EGB  [SOT23-5]
U151  PCA9543  [soic14-50-157]
U154  AP7333  [SOT23R]
U170  TPD8E003  [WSON8EP]
U171  TPD8E003  [WSON8EP]
U172  TPD8E003  [WSON8EP]
U173  TPD8E003  [WSON8EP]
U175  CM1293A  [SC-74]
U176  CM1293A  [SC-74]

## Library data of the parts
U1 = PXA168_1: Desc: IC App Processor SOC; Part Num: 88AP166SA0-BJD2C008; Vendor: Marvell
C10 C11 = CAP_NP_0: Desc: CAP 10pF 5% 0402 50V NP0; Part Num: GRM1555C1H100JZ01D; Vendor: Murata; mfg: Murata; mfg_pn: GRM1555C1H100JZ01D
C211 = CAP_NP_2: Desc: CAP CER 4.7UF 6.3V 20% X5R 0402; Part Num: CL05A475MQ5NRNC; Vendor: TDK; mfg: TDK; mfg_pn: C1005X7R1A104K
Q2 Q24 Q64 Q121 = PMOS3: Desc: MOSFET P-CH 20V 2.4A SSOT3; Vendor: FAIRCHILD
Q12 Q29 Q30 Q101-Q104 Q109 Q110 Q118 Q119 = NMOS3: Desc: MOSFET N-CH 25V 220MA SOT-23; Vendor: FAIRCHILD
R17 R18 R31-R35 R70 R383-R387 R427-R430 R441 R442 R450 R451 = Res_0: Desc: RES 10K OHM 1/10W 5% 0402 SMD; Mfr: Generic; Part Num: ERJ-2GEJ103X; Vendor: Panasonic
R21 = Res_0: Desc: RES 6.04K OHM 1/10W 1% 0603 SMD; Mfr: Generic; Part Num: ERJ-3EKF6041V; Vendor: Panasonic
R22 = Res_0: Desc: RES 0.0 OHM 1/10W 0402 SMD; Mfr: Generic; Part Num: ERJ-2GE0R00X; Vendor: Panasonic
R23 R24 R327 R328 = Res_0: Desc: RES 0.0 OHM 1/10W 0402 SMD; Mfr: Generic; Part Num: ERJ-2GE0R00X; Vendor: Panasonic; ccc: RES 0.0 OHM 1/10W 0402 SMD
R25 = Res_0: Desc: RES 1.00M OHM 1/16W 1% 0402 SMD; Mfr: Generic; Part Num: MCR01MZPF1004; Vendor: Panasonic
R77 = R_0: Desc: RES 10K OHM 1/10W 5% 0402 SMD; Mfr: Generic; Part Num: ERJ-2GEJ103X; Vendor: Panasonic
R308 R309 R325 R326 R382 R476 R501 R502 R518 R547 R557 R558 = Res_0: Desc: RES 10K OHM 1/10W 5% 0402 SMD; Part Num: ERJ-2GEJ103X; Vendor: Panasonic
Y1 = OSC5_1.5: Desc: CRYSTAL 26.000 MHZ 18PF SMD; Part Num: 7M26070013; Vendor: TXC
C320 C322 C331 = CAP_NP: CAP CER .10UF 10V X5R 10% 0402; Desc: CAP CER .10UF 10V X7R 0402; Distributor: Digi-Key; Distributor Part Number: 445-1265-1-ND; Manufacturer: C1005X5R1A104K; Manufacturer Part Number: CAP CER .10UF 10V X5R 10% 0402; Part Num: C1005X7R1A104K; Vendor: TDK
C321 C327 = CAP_NP: CAP CER .10UF 10V X5R 10% 0402; Desc: CAP CER 2200PF 10V 20% X7R 0402; Distributor: Digi-Key; Distributor Part Number: 445-1265-1-ND; Manufacturer: C1005X5R1A104K; Manufacturer Part Number: CAP CER .10UF 10V X5R 10% 0402; Part Num: CL05B222MP5NNNC; Vendor: Samsung
CM1 CM2 = COM_CHOCK_USB_0: Desc: Common Mode Filters / Chokes 0805 90ohm@100MHz Tol 25%; OPTION: LIPO; Part Num: DLW21HN900SQ2L; Vendor: Murata
D12 D14 D29 D30 = DIODE_SCHOTTKY: Desc: DIODE ESD PROT 1A 100V MICROSMP; Part Num: MSE1PB-M3/89A; Vendor: Vishay
D32 = Diodesot23: Desc: DIODE SCHOTTKY 30V 0.2A SOT23-3; Vendor: Fairchild
J1 = USB_MICRO_AB: CONN RCPT MICRO USB AB R/A SMD; Desc: CONN RCPT MCR USB AB SMD TH SHLL; MANUFACTURER: MOLEX; MFR PN: 0476420001; Part Num: ZX62RD-AB-5P8; Vendor: Hirose
J8 J32 J34 = PIC_DEBUG_PAD: Desc: CONN FFC/FPC 5POS 1MM VERT T/H; Part Num: 52806-0510; Vendor: Molex
R102 R345 R490 R491 = Res_0: Desc: RES 0.0 OHM 1/10W 0402 SMD; Mfr: Generic; OPTION: LIPO; Part Num: ERJ-2GE0R00X; Vendor: Panasonic; ccc: RES 0.0 OHM 1/10W 0402 SMD
R337 R381 R424 R425 = Res_0: Desc: RES 47K OHM 1/10W 5% 0402 SMD; Part Num: ERJ-2GEJ473X; Vendor: Panasonic
R519 R523 R532-R535 = Res_0: Desc: RES 1K OHM 1/10W 1% 0402 SMD; Mfr: Generic; Part Num: ERJ-2RKF1001X; Vendor: Panasonic
R542 R548 = Res_0: Desc: RES 0.01 OHM 1/4W 1% 0603 SMD; Part Num: ERJ-M03NF10MV; Vendor: Panasonic
SW5 SW13 = SW_PUSHBUTTON-SPST-2_0: LT SWITCH SIDE PUSH SMD; Desc: SWITCH TACTILE SPST-NO 0.05A 12V; Manufacturer: Panasonic; Manufacturer_PN: EVQ-PUJ02K; Vendor: Tyco
U159 = PIC12F508: Part Num: PIC12F508I/MC
C181 = CAP_NP_2: Desc: CAP CER 22UF 4V 20% X5R 0603; Part Num: AMK107BJ226MA-T; Vendor: Taiyo
C184 C339 = CAP_NP_2: Desc: CAP CER .10UF 10V X7R 0402; Part Num: C1005X7R1A104K; Vendor: TDK; mfg: TDK; mfg_pn: C1005X7R1A104K
C185 = CAP_NP_2: Desc: CAP CER 10UF 10V 10% X5R 0603; Part Num: C1608X5R1A106K080AC; Vendor: TDK
C189 C192 = CAP_NP: CAP CER 10UF 10V X5R 20% 0603; Desc: CAP CER 10UF 10V 10% X5R 0603; Distributor: DIGI-KEY; Distributor_Part_Number: 587-2562-2-ND; Mfr: Taiyo Yuden; Mfr_Part_Number: LMK107BJ106MALTD; Part Num: C1608X5R1A106K080AC; Part_Number: 587-2562-2-ND; Status: PN_APPLYED; Temperature_Coefficient: X5R; Tolerance: +/-20%; Vendor: TDK; part_type: Capacitor
C190 C191 = CAP_NP: CAP CER .22UF 6.3V X5R 0201; Desc: CAP CER .22UF 6.3V X5R 0201; Distributor: DIGI-KEY; Distributor_Part_Number: 587-1819-2-ND; Mfr: Taiyo Yuden; Mfr_Part_Number: JMK063BJ224MP-F; Part Num: JMK063BJ224MP-F; Part_Number: 587-1819-2-ND; Status: PN_APPLYED; Temperature_Coefficient: X5R; Tolerance: +/-20%; Vendor: Taiyo; part_type: Capacitor; Datasheet: \\sh4-dt-609\work\CIS\datasheet\CAPACITORS\dlmk_e.pdf
C193 C194 = CAP_NP: CAP CER 22UF 4V X5R 0603; ALT_SYMBOLS: PORTABLE_CAP_0603; Desc: CAP CER 22UF 4V 20% X5R 0603; Distributor: DIGI-KEY; Distributor_Part_Number: 490-5526-2-ND; Mfr: Murata; Mfr_Part_Number: GRM188R60G226MEA0L; Part Num: AMK107BJ226MA-T; Part_Number: 490-5526-2-ND; Status: PN_APPLYED; Temperature_Coefficient: X5R; Tolerance: +/-20%; Vendor: Taiyo; part_type: Capacitor; Datasheet: \\sh4-dt-609\work\CIS\datasheet\CAPACITORS\djmk_e.pdf
C195 = CAP_NP: CAP CER 10UF 6.3V X5R 0603; Desc: CAP CER 10UF 6.3V 20% X5R 0402; Distributor: DIGI-KEY; Distributor_Part_Number: 490-3896-2-ND; Mfr: Murata; Mfr_Part_Number: GRM188R60J106ME47D; Part Num: C1005X5R0J106M050BC; Part_Number: 490-3896-2-ND; Status: PN_APPLYED; Temperature_Coefficient: X5R; Tolerance: +/-20%; Vendor: TDK; part_type: Capacitor; Datasheet: \\sh4-dt-609\work\CIS\datasheet\CAPACITORS\GRM188R60J106ME47.pdf
C196 = CAP_NP: CAP CER 1UF 10V X5R 0402; Desc: CAP CER 1UF 10V 10% X5R 0402; Distributor: Digi-Key; Distributor_Part_Number: 490-3890-2-ND; Mfr: Murata Electronics North America; Mfr_Part_Number: GRM155R61A105KE15D; Part Num: C1005X5R1A105K050BB; Part_Number: 490-3890-2-ND; Status: PN_APPLYED; Temperature_Coefficient: X5R; Tolerance: +/-10%; Vendor: TDK; ccc: CAP CER 1UF 10V 10% X5R 0402; part_type: Capacitor; Datasheet: \\sh4-dt-609\work\CIS\datasheet\CAPACITORS\GRM155R61A105KE15.pdf
C328 = CAP_NP: CAP CER 4.7UF 6.3V +/-10% X5R 0603; Desc: CAP CER 4.7UF 6.3V 10% X5R 0603; Manufacturer: Murata; Manufacturer Part Number: GRM188R60J475KE19D; Part Num: GRM188R60J475KE19D; Vendor: Murata
C329 C332 C333 = CAP_NP: CAP CER 4.7UF 6.3V +/-10% X5R 0603; Desc: CAP CER 4.7UF 10V 10% X5R 0603; Manufacturer: Murata; Manufacturer Part Number: GRM188R60J475KE19D; Part Num: LMK107BJ475KA-T; Vendor: Taiyo
C330 = CAP_NP: CAP CER 10uF 6.3V X5R +/-10% 0603; Desc: CAP CER 10UF 6.3V 20% X5R 0402; Manufacturer: Murata; Manufacturer Part Number: GRM188R60J106ME47D; Part Num: C1005X5R0J106M050BC; Vendor: TDK
L10 = INDUCTOR_0: Desc: INDUCTOR 1.0UH 2.0A 30% SMD; Part Num: FLF3215T-1R0N; Vendor: TDK
L11 = INDUCTOR: Desc: INDUCTOR POWER 1.2UH 3.8A SMD; Mfr: Toko; Mfr_Part_Number: NLC565050T-1R2K-P; Part Num: VLC5020T-1R2N; Part_Number: NLC565050T-1R2K-P; Status: PN_APPLYED; Vendor: TDK; part_type: Inductor; Datasheet: \\SH4-DT-609\WORK\CIS\datasheet\FDSD0412_Sept2011.pdf
L12 = INDUCTOR: INDUCTOR 1.5uH 20%, max thermal current 2.05A SMD; ALT_SYMBOLS: INDUCTOR_3012_Large; Desc: INDUCTOR POWER 1.5UH 2.6A SMD; Mfr: Toko; Mfr_Part_Number: MDT2520-CN1R5M; Part Num: IFSC1008ABER1R5M01; Part_Number: IFSC1008ABER1R5M01; Status: PN_APPLYED; Vendor: Vishay; part_type: Inductor; Datasheet: \\SH4-DT-609\WORK\CIS\datasheet\mdt2520_cn.pdf
L35 = INDUCTOR: MDT2520-CN Type,1.0uH,85mΩ，H=1.2mm,L=2.5mm,W=2.0mm; Desc: INDUCTOR POWER 1UH 2.6A SMD; Manufacturer: TOKO; Manufacturer Part Number: MDT2520-CN1R0M; Part Num: IFSC1008ABER1R0M01; Vendor: Vishay
R109 R112 R443 R444 R559 = R_0: Desc: RES 0.0 OHM 1/10W 0402 SMD; Mfr: Generic; Part Num: ERJ-2GE0R00X; Vendor: Panasonic
R110 R111 R116 R120 = R_0: Desc: RES 100K OHM 1/16W 5% 0402 SMD; Mfr: Generic; Part Num: CRCW0402100KJNED; Vendor: Vishay
R113 R114 = R_0: Desc: RES 51K OHM 1/10W 5% 0402 SMD; Mfr: Generic; Part Num: ERJ-2GEJ513X; Vendor: Panasonic
R115 R119 R136 R390 = R_0: Desc: RES 0.0 OHM 1/10W 0603 SMD; Mfr: Generic; Part Num: ERJ-3GEY0R00V; Vendor: Panasonic
R117 = R_0: Desc: RES 10 OHM 1/10W 5% 0402 SMD; Mfr: Generic; Part Num: ERJ-2GEJ100X; Vendor: Panasonic
R118 = Res_0: Desc: RES 1K OHM 1/10W 1% 0402 SMD; Mfr: Generic; Part Num: ERJ-2RKF1001X; Vendor: Panasonic; d: RES 1K OHM 1/10W 1% 0402 SMD
R121 R134 R389 = Res_0: Desc: RES 100K OHM 1/16W 5% 0402 SMD; Part Num: CRCW0402100KJNED; Vendor: Vishay
R122 = R: RES 10.0 OHM 1/16W 1% 0402 SMD; Desc: RES 10 OHM 1/10W 5% 0402 SMD; Distributor: Digikey; Distributor_Part_Number: 311-10.0LRTR-ND; Mfr: Yageo; Mfr_Part_Number: RC0402FR-0710RL; Part Num: ERJ-2GEJ100X; Part_Number: 311-10.0LRTR-ND; Power: 0.063W, 1/16W; Status: PN_APPLYED; Temperature_Coefficient: +/-200ppm/C; Tolerance: +/-1%; Vendor: Panasonic; part_type: Resistor; Datasheet: \\sh4-dt-609\work\CIS\datasheet\RESISTORS\PYu-RC0402_51_RoHS_L_6.pdf
R388 = RES_169K_1p_1: RES 100K OHM 1/10W 5% 0603 SMD; Desc: RES 100K OHM 1/16W 5% 0402 SMD; Distributor: Digi-Key; Distributor Part Number: P100KGTR-ND; Distributor_Part_Number: P100KGTR-ND; Manufacturer: Panasonic - ECG; Manufacturer Part Number: ERJ-3GEYJ104V; Part Num: CRCW0402100KJNED; Percent: 5%; Tolerance: 5%; Vendor: Vishay; Wattage: 1/10W
U16 = 88PG867: Desc: IC Power, Dual 3A/1A buck; Part Num: 88PG867-HB0-NNY2C00; Vendor: Marvell
U133 = 88PG8111-1: Desc: IC power, 500mA buck 50mA LDO; Part Num: 88PG8211A2-NXS2C000; Vendor: Marvell
VR1 = 88PG818_0: Desc: IC Power Switching; Part Num: 88PG839-A1-NAE2C000; Vendor: Marvell
C110 C112 C326 C340-C342 C347-C349 C391 = CAPACITOR_NON-POL: Desc: CAP CER .10UF 10V X7R 0402; OPTION: DBG; Part Num: C1005X7R1A104K; Vendor: TDK
C325 C346 C364 C366 C368 = CAP_NP_2: Desc: CAP CER 2.2UF 10V 10% X5R 0402; Part Num: C1005X5R1A225K; Vendor: TDK
C381 = CAP_NP_0: Desc: CAP CER 4.7UF 10V 10% X5R 0603; OPTION: LIPO; Part Num: LMK107BJ475KA-T; Vendor: Taiyo
J7 = CN_JTAG_MARVELL16: Desc: CONN SOCKET 2.54MM 16POS GOLD; OPTION: DBG; Part Num: HLE-108-02-F-DV; Vendor: Samtec
J33 = USB_MICRO_AB: Desc: CONN RCPT MINIUSB B 5POS SMD R/A; Part Num: 0513870530; Vendor: MOLEX
LED13 = LED_0: Colour: *LED0603; Desc: LED GREEN CLEAR THIN 0603 SMD; OPTION: DBG; Part Num: LTST-C191KGKT; Vendor: Liteon
R196 R257 = RESISTOR: OPTION: DBG; Part Num: ERJ-2GEJ220X; Vendor: Panasonic; desc: RES 22 OHM 1/10W 5% 0402 SMD
R253 = RESISTOR: Desc: RES 4.7K OHM 1/10W 5% 0402 SMD; OPTION: DBG; Part Num: ERJ-2GEJ472X; Vendor: Panasonic
R270 = Res_0: Desc: RES 2.2K OHM 1/10W 5% 0402 SMD; OPTION: DBG; Part Num: ERJ-2GEJ222X; Part Number: R1030402; Vendor: Panasonic
R554-R556 = Res_0: Desc: RES 0.0 OHM 1/10W 0402 SMD; Part Num: ERJ-2GE0R00X; Vendor: Panasonic
U134 = FT234-DFN12: Part Num: FT234XD-R
C188 C367 C369 = CAP_NP_2: Desc: CAP CER 10UF 10V 10% X5R 0603; Part Num: C1005X5R1A225K; Vendor: TDK
FB48-FB50 = FERRITE_BEAD_0: Desc: FERRITE CHIP 120 OHM 3000MA 0603; Part Num: BLM18KG121TN1; Vendor: Murata
J36 J39 = CON8: Desc: CONN HEADER FEMALE 8POS .1" GOLD; Part Num: SSM-108-F-SV; Vendor: Samtec
Q66-Q73 Q82-Q89 = CMOS-DUAL: Desc: MOSFET N/P-CH 20V 600/350 SC89-6; Vendor: Vishay
R347-R362 R397-R412 = R_0: Desc: RES 10K OHM 1/20W 5% 0201 SMD; Mfr: Generic; Part Num: ERJ-1GEJ103C; Vendor: Panasonic
R393 R395 R418 R419 = R_0: Desc: RES 1K OHM 1/10W 1% 0402 SMD; Mfr: Generic; Part Num: ERJ-2RKF1001X; Vendor: Panasonic; d: RES 1K OHM 1/10W 1% 0402 SMD
R468-R471 R505 R510-R513 R536 = Res_0: Desc: RES 10K OHM 1/20W 5% 0201 SMD; Part Num: ERJ-1GEJ103C; Vendor: Panasonic
R472-R475 = Res_0: Desc: RES 10K OHM 1/20W 5% 0201 SMD; Mfr: Generic; Part Num: ERJ-1GEJ103C; Vendor: Panasonic
U135 U143 = PIC16F1508QFN
U136 U137 U144 U145 = 74HC4094
U131 U132 U141 U142 U147 U148 = RT9517SOT23-5: Desc: IC PWR SW USB 1.1A SOT23-5; Vendor: Richtek
U175-U180 = CM1293A: Desc: TVS DIODE 5.5VWM 12VC SOT26; Part Num: D5V0F4U6SO-7; Vendor: Diodes
C187 = CAP_NP: Desc: CAP CER .10UF 10V X7R 0402; Function Code: VGA; Part Num: C1005X7R1A104K; Part Number: CH41006K911; Vendor: TDK
C362 C363 C392 = CAP_NP_0: Desc: CAP CER 1UF 10V 10% X5R 0402; OPTION: LIPO; Part Num: C1005X5R1A105K050BB; Vendor: TDK; ccc: CAP CER 1UF 10V 10% X5R 0402
C370 = CAP_NP_1: Desc: CAP CER .10UF 10V X7R 0402; Part Num: C1005X7R1A104K; Vendor: TDK
J35 = CON50A: Desc: CONN RCPT 50POS .100" DBL GOLD BOTTOM ENTRY; Part Num: BSW-125-04-L-D; Vendor: Samtec
U151 = PCA9543: Desc: IC I2C SWITCH 2CH 14-TSSOP; MFG: NXP; MFG_PN: PCA9543AD,118; Part Num: PCA9543AD,118; Vendor: NXP
U154 = AP7333
U170-U173 = TPD8E003

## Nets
FLX1_3VENH/5VENL: Q118.G R419.2 U148.4(EN/~{EN}) ; also on sheet 8
FLX2_3VENH/5VENL: Q119.G R395.1 U142.4(EN/~{EN}) ; also on sheet 8
GND: C10.2 C11.2 C110.2 C112.2 C181.2 C184.2 C185.2 C187.2 C188.2 C189.1 C190.1 C191.1 C192.2 C193.2 C194.2 C195.1 C196.1 C320.2 C322.2 C325.2 C326.2 C328.1 C329.1 C330.1 C331.2 C332.1 C333.1 C339.2 C340.2 C341.2 C342.2 C346.2 C347.2 C348.2 C349.2 C362.2 C363.2 C364.2 C366.2 C367.2 C368.2 C369.2 C370.2 C381.2 C391.2 C392.2 D12.1(ANODE) D14.1(ANODE) D29.1(ANODE) D30.1(ANODE) J1.5(GND) J1.T3(TAB) J1.T4(TAB) J1.T5(TAB) J1.T6(TAB) J7.4(GND) J7.6(GND) J7.8(GND) J7.10(GND) J7.12(GND) J7.14(GND) J7.16(GND) J8.3(VSS) J32.3(VSS) J33.5(GND) J33.T3(TAB) J33.T4(TAB) J33.T5(TAB) J33.T6(TAB) J34.3(VSS) J35.1 J35.2 J35.13 J35.14 J35.26 J35.32 J35.35 J35.36 J35.41 J35.42 J35.45 J35.46 Q12.S Q66.1(S) Q67.1(S) Q68.1(S) Q69.1(S) Q70.1(S) Q71.1(S) Q72.1(S) Q73.1(S) Q82.1(S) Q83.1(S) Q84.1(S) Q85.1(S) Q86.1(S) Q87.1(S) Q88.1(S) Q89.1(S) Q118.S Q119.S R18.2 R21.2 R22.1 R23.1 R24.1 R70.2 R77.2 R110.2 R112.2 R113.2 R114.2 R116.1 R347.1 R349.1 R351.1 R353.1 R355.1 R357.1 R359.1 R361.1 R384.1 R386.2 R389.2 R395.2 R398.1 R400.1 R402.1 R404.1 R405.1 R407.1 R409.1 R411.1 R419.1 R443.1 R444.1 R505.1 R511.2 R512.2 R536.1 R547.1 R558.1 SW5.2 SW5.4 SW13.1 SW13.3 U16.1(PGND) U16.2(PGND1_1) U16.7(PGND1_2) U16.8(PGND) U16.12(PGND) U16.13(PGND2_1) U16.20(SGND) U16.24(PGND) U16.EP U131.2(GND) U132.2(GND) U133.2(SGND) U133.5(PGND2) U133.12(SGND12) U133.21(PGND) U134.5(GND) U134.13(GNDPAD) U135.17(VSS) U135.EP(VSS) U136.8(GND) U137.8(GND) U141.2(GND) U142.2(GND) U143.17(VSS) U143.EP(VSS) U144.8(GND) U145.8(GND) U147.2(GND) U148.2(GND) U151.7(VSS) U154.1(GND) U159.8(VSS) U159.EP(PAD) U170.EP(GND) U171.EP(GND) U172.EP(GND) U173.EP(GND) U175.2(NV) U176.2(NV) U177.2(NV) U178.2(NV) U179.2(NV) U180.2(NV) VR1.4(SGND) VR1.13(PGND) ; also on sheet 1 2 3 4 7 8 9
GND_EN1: Q66.2(G) R347.2 U137.14(QP4)
GND_EN2: Q67.2(G) R349.2 U137.13(QP5)
GND_EN3: Q68.2(G) R351.2 U137.12(QP6)
GND_EN4: Q69.2(G) R353.2 U137.11(QP7)
GND_EN5: Q70.2(G) R355.2 U136.14(QP4)
GND_EN6: Q71.2(G) R357.2 U136.13(QP5)
GND_EN7: Q72.2(G) R359.2 U136.12(QP6)
GND_EN8: Q73.2(G) R361.2 U136.11(QP7)
GND_EN9: Q82.2(G) R400.2 U144.14(QP4)
GND_EN10: Q83.2(G) R402.2 U144.13(QP5)
GND_EN11: Q84.2(G) R404.2 U144.12(QP6)
GND_EN12: Q86.2(G) R405.2 U144.11(QP7)
GND_EN13: Q87.2(G) R407.2 U145.14(QP4)
GND_EN14: Q88.2(G) R409.2 U145.13(QP5)
GND_EN15: Q89.2(G) R411.2 U145.12(QP6)
GND_EN16: Q85.2(G) R398.2 U145.11(QP7)
V1P5_DDR: R119.2 ; also on sheet 1 4
V1P8: R390.1 ; also on sheet 1 2 3
V3P3: C370.1 J7.1(V_REF) J7.2(V_SUP) Q2.S Q29.G Q30.G Q101.G Q102.G Q103.G Q104.G Q109.G Q110.G R17.1 R31.1 R32.1 R33.1 R34.1 R35.1 R115.2 R270.2 R325.2 R326.2 R424.1 R427.1 R428.1 R429.1 R430.1 R441.1 R442.1 R450.1 R451.1 R468.2 R469.2 R470.2 R471.2 R476.2 R501.2 R502.2 R556.1 R559.2 U131.5(VIN) U142.5(VIN) U148.5(VIN) U151.14(VDD) ; also on sheet 1 2 3 4 7 8 9
V3P3_USB_A: C211.1 ; also on sheet 1
V3P3AEXP: C363.1 J35.49 U154.2(VOUT)
V3P3EXP: C187.1 J35.25 U131.1(VOUT)
V3P3FTDI: C112.1 R555.2 R556.2 R557.2 U134.9(VCCIO)
V3P3U: C110.1 R555.1 U134.3(3V3OUT)
V5P0AEXP: C364.1 FB48.1 J35.50
V5P0EXP: C188.1 FB48.2 U132.1(VOUT) U175.5(VP) U176.5(VP)
VBUS_OTG: J1.1(VBUS) R548.2
VBUS_SER: C325.1 C326.1 C381.1 J33.1(VBUS) R253.1 R542.2 U134.4(VCC)
VCC_FLEX1: C340.1 C341.1 C342.1 C346.1 C366.1 FB49.2 J8.2(VDD) Q66.4(S) Q67.4(S) Q68.4(S) Q69.4(S) Q70.4(S) Q71.4(S) Q72.4(S) Q73.4(S) R348.1 R350.1 R352.1 R354.1 R356.1 R358.1 R360.1 R362.1 R474.1 R475.1 R510.2 U135.18(VDD) U136.16(VCC) U137.16(VCC)
VCC_FLEX1S: C367.1 FB49.1 U141.1(VOUT) U148.1(VOUT)
VCC_FLEX2: C347.1 C348.1 C349.1 C368.1 FB50.2 J34.2(VDD) Q82.4(S) Q83.4(S) Q84.4(S) Q85.4(S) Q86.4(S) Q87.4(S) Q88.4(S) Q89.4(S) R397.1 R399.1 R401.1 R403.1 R406.1 R408.1 R410.1 R412.1 R472.1 R473.1 R513.2 U143.18(VDD) U144.16(VCC) U145.16(VCC)
VCC_FLEX2S: C369.1 FB50.1 U142.1(VOUT) U147.1(VOUT)
VIN: Q121.D R542.1 R548.1 ; also on sheet 9
A10: R442.2 R444.2 U151.1(A0)
A11: R441.2 R443.2 U151.2(A1)
AP_AP2WLAN_WAKEUP: U1.D14(MFP23_(GPO_UART/SD#)) ; also on sheet 2
AP_ISET: R21.1 U1.R17(A_ISET(USB))
AP_JTAG_SEL: Q2.D R17.2 R18.1 U1.N2(JTAG_SEL_(FN0))
AP_PRI_TCK: J7.9(TCK) U1.M2(PRI_TCK_(FN0))
AP_PRI_TDI: J7.5(TDI) U1.L4(PRI_TDI_(FN0))
AP_PRI_TDO: LED13.2(K) R257.1 U1.M3(PRI_TDO_(FN0))
AP_PRI_TMS: J7.7(TMS) U1.M1(PRI_TMS_(FN0))
AP_TRST_N: J7.3(TRST#) U1.M4(TRST_N_(FN0))
AP_UART2_CBUS0: R554.2 ; also on sheet 8
AP_UART2_RX: R196.1 U1.A2(MFP88(UART2_RTX_D)_(FN2/3)) ; also on sheet 7
AP_UART2_TX: U1.D4(MFP89(UART2_TRX_D)_(FN2/3)) U134.10(RXD) ; also on sheet 7
AUDIO_ADCDAT: U1.J3(MFP116(SSP1_RTXD)_(FN2)) ; also on sheet 3
AUDIO_BCLK: U1.J4(MFP115(SSP1_CLK)_(FN1)) ; also on sheet 3
AUDIO_DACDAT: U1.J2(MFP117(SSP1_RTXD)_(FN2)) ; also on sheet 3
AUDIO_LRCK: U1.H1(MFP114(SSP1_FRM)_(FN1)) ; also on sheet 3
AUDIO_MCLK: U1.H2(MFP113(SSP_SYSCLK)_(FN6)) ; also on sheet 3
BSTEN_H/CHRGEN_L: R519.1 ; also on sheet 9
CE156ON_L: U1.K18(MFP43_(GPI_AU_JD#)) ; also on sheet 3
CON_USBDM: CM2.3(OUT2) D29.2(CATHODE) J33.2(D-) R491.2
CON_USBDP: CM2.4(IN2) D30.2(CATHODE) J33.3(D+) R490.2
CP1: U135.5(RC6) U136.3(CP) U137.3(CP)
CP2: U143.5(RC6) U144.3(CP) U145.3(CP)
D_1_4: U135.3(RC4) U137.2(D)
D_5_8: U135.2(RC5) U136.2(D)
D_9_12: U143.3(RC4) U144.2(D)
D_13_16: U143.2(RC5) U145.2(D)
EN2A: R121.1 U16.23(EN2)
EN2B: R383.2 U133.11(EN2)
ENLDO: R386.1 U133.16(ENLDO)
EXP_OC_L: U131.3(~{FLG}) U132.3(~{FLG}) ; also on sheet 8
EXT_SCL: J35.29 Q110.D R427.2 U171.4(I/O4)
EXT_SCL3: Q110.S R501.1 U151.10(SC1)
EXT_SDA: J35.27 Q109.D R428.2 U171.3(I/O3)
EXT_SDA3: Q109.S R502.1 U151.9(SD1)
FLX1_OC_L: U141.3(~{FLG}) U148.3(~{FLG}) ; also on sheet 8
FLX2_OC_L: U142.3(~{FLG}) U147.3(~{FLG}) ; also on sheet 8
FT_RST_L: C391.1 R253.2 R558.2 U134.2(RESETL)
GPIO_PWR_BTN: Q29.S R325.1 R327.1 U1.G17(MFP53_(GPO_SLP_GNT#)_(FN0))
GPIO_PWR_CLK: Q30.S R326.1 R328.1 U1.G18(MFP52_(GPI_SLP_REQ#)_(FN0))
HIB_EN: R382.2 U159.3(GP4) ; also on sheet 9
ICSPCLK: J32.5(PGC) R518.2 R519.2 U159.6(GP1/ICSPC)
ICSPCLK (page P14: Front access 8 pin conn 1): J8.5(PGC) R532.2 U135.15(RA1/AN1)
ICSPCLK (page P15: Front access 8 pin conn 2): J34.5(PGC) R534.2 U143.15(RA1/AN1)
ICSPDAT: J32.4(PGD) R523.1 U159.7(GP0/ICSPD)
ICSPDAT (page P14: Front access 8 pin conn 1): J8.4(PGD) R533.2 U135.16(RA0/AN0)
ICSPDAT (page P15: Front access 8 pin conn 2): J34.4(PGD) R535.2 U143.16(RA0/AN0)
INT_PCONN: R476.1 U135.7(RB7) U143.7(RB7) U151.4(~{INT0})
INT_SCL1: Q102.D R474.2 U135.8(RB6/SCL)
INT_SCL2: Q103.D R472.2 U143.8(RB6/SCL)
INT_SCL3: Q102.S Q103.S R430.2 R468.1 R471.1 U151.6(SC0)
INT_SDA1: Q101.D R475.2 U135.10(RB4/SDA)
INT_SDA2: Q104.D R473.2 U143.10(RB4/SDA)
INT_SDA3: Q101.S Q104.S R429.2 R469.1 R470.1 U151.5(SD0)
INTR11: R559.1 U151.8(~{INT1})
LOW_BATT: R523.2 U1.A16(MFP19_(GPI_TSC_IRQ#)) ; also on sheet 9
MFP37: J35.4 U1.L15(MFP37_(CCIC_DAT7)_(FN4)) U172.1(I/O1)
MFP38: J35.6 U1.L16(MFP38_(CCIC_DAT6)_(FN4)) U172.2(I/O2)
MFP39: J35.8 U1.M15(MFP39_(CCIC_DAT5)_(FN4)) U172.3(I/O3)
MFP40: J35.10 U1.K15(MFP40_(CCIC_DAT4)_(FN4)) U172.4(I/O4)
MFP41: J35.12 U1.K16(MFP41_(CCIC_DAT3)_(FN4)) U172.8(I/O8)
MFP42: J35.16 U1.K17(MFP42_(CCIC_DAT2)_(FN4)) U172.7(I/O7)
MFP44: J35.18 U1.J15(MFP44_(CCIC_DAT1)_(FN4)) U172.6(I/O6)
MFP45: J35.20 U1.J16(MFP45_(CCIC_DAT0)_(FN4)) U172.5(I/O5)
MFP46: J35.22 U1.J17(MFP46_(CCIC_VSYNC)_(FN4)) U173.1(I/O1)
MFP48: J35.24 U1.H18(MFP48_(CCIC_HSYNC)_(FN4)) U173.2(I/O2)
MFP49: J35.15 U1.H17(MFP49_(GPI_SD_REQ#)_(FN0)) U170.8(I/O8)
MFP50: J35.17 U1.H16(MFP50_(CCIC_VCLK)_(FN4)) U170.7(I/O7)
MFP51: J35.19 U1.H15(MFP51_(GPO_SD_GNT#)_(FN0)) U170.6(I/O6)
MFP54: J35.21 U1.G16(MFP54_(CCIC_MCLK)_(FN4)) U171.1(I/O1)
MFP55: J35.23 U1.G15(MFP55_(CCIC_PCLK)_(FN4)) U171.2(I/O2)
MFP90: J35.3 U1.B2(MFP90(MMC2_DAT3)_(FN1)) U170.1(I/O1) ; also on sheet 7
MFP91: J35.5 U1.C3(MFP91(MMC2_DAT2)_(FN1)) U170.2(I/O2) ; also on sheet 7
MFP92: J35.7 U1.A1(MFP92(MMC2_DAT1)_(FN1)) U170.3(I/O3) ; also on sheet 7
MFP93: J35.9 U1.B1(MFP93(MMC2_DAT0)_(FN1)) U170.4(I/O4) ; also on sheet 7
MFP94: J35.11 U1.C2(MFP95(MMC2_CLK)_(FN1)) U170.5(I/O5)
MFP96_PWM3: J35.28 U1.E4(MFP96_(GPIO)_(FN0)) U173.8(I/O8)
MFP97_PWM2: J35.34 U1.C1(MFP97_(PWM2)_(FN1)) U173.6(I/O6)
MFP104_PWM4: J35.30 U1.E1(MFP104_(PWR_CTL_WIFI)) U173.7(I/O7)
MFP_I2C_INTR: R451.2 U151.11(~{INT}) ; also on sheet 8
MFP_SCL: R32.2 U1.F3(MFP103(I2C_SCL)_(FN1)) U151.12(SCL) ; also on sheet 3 7 9
MFP_SDA: R31.2 U1.E2(MFP102(I2C_SDA)_(FN1)) U151.13(SDA) ; also on sheet 3 7 9
MODE2: R384.2 U133.4(MODE2)
OE1: R505.2 U135.19(RA5) U136.15(OE) U137.15(OE)
OE2: R536.2 U143.19(RA5) U144.15(OE) U145.15(OE)
OTG_PWRH: U1.D13(MFP25) ; also on sheet 9
PCA_RST: C392.1 R450.2 U1.J18(MFP47) U151.3(~{RST})
PIN1: J35.47 J36.1 Q66.3(D) Q66.6(D) R533.1 U175.1(CH1) U177.1(CH1)
PIN2: J35.48 J36.2 Q67.3(D) Q67.6(D) R532.1 U176.1(CH1) U177.3(CH2)
PIN3: J35.43 J36.3 Q68.3(D) Q68.6(D) U135.14(RA2/AN2) U175.3(CH2) U177.4(CH3)
PIN4: J35.44 J36.4 Q69.3(D) Q69.6(D) U135.20(RA4/AN3) U176.3(CH2) U177.6(CH4)
PIN5: J35.39 J36.5 Q70.3(D) Q70.6(D) U135.13(RC0/AN4) U175.4(CH3) U178.6(CH4)
PIN6: J35.40 J36.6 Q71.3(D) Q71.6(D) U135.12(RC1/AN5) U176.4(CH3) U178.4(CH3)
PIN7: J35.37 J36.7 Q72.3(D) Q72.6(D) U135.11(RC2/AN6) U175.6(CH4) U178.3(CH2)
PIN8: J35.38 J36.8 Q73.3(D) Q73.6(D) U135.4(RC3/AN7) U176.6(CH4) U178.1(CH1)
PIN9: J39.1 Q82.3(D) Q82.6(D) R535.1 U179.1(CH1)
PIN10: J39.2 Q83.3(D) Q83.6(D) R534.1 U179.3(CH2)
PIN11: J39.3 Q84.3(D) Q84.6(D) U143.14(RA2/AN2) U179.4(CH3)
PIN12: J39.4 Q86.3(D) Q86.6(D) U143.20(RA4/AN3) U179.6(CH4)
PIN13: J39.5 Q87.3(D) Q87.6(D) U143.13(RC0/AN4) U180.6(CH4)
PIN14: J39.6 Q88.3(D) Q88.6(D) U143.12(RC1/AN5) U180.4(CH3)
PIN15: J39.7 Q89.3(D) Q89.6(D) U143.11(RC2/AN6) U180.3(CH2)
PIN16: J39.8 Q85.3(D) Q85.6(D) U143.4(RC3/AN7) U180.1(CH1)
PWR_BTN: C322.1 J32.1(VPP) Q29.D R309.2 R327.2 SW13.2 SW13.4 U159.4(GP3/MCLR)
PWR_CLK: Q30.D R328.2 U159.5(GP2)
PWR_EN1: Q66.5(G) R348.2 U137.4(QP0)
PWR_EN2: Q67.5(G) R350.2 U137.5(QP1)
PWR_EN3: Q68.5(G) R352.2 U137.6(QP2)
PWR_EN4: Q69.5(G) R354.2 U137.7(QP3)
PWR_EN5: Q70.5(G) R356.2 U136.4(QP0)
PWR_EN6: Q71.5(G) R358.2 U136.5(QP1)
PWR_EN7: Q72.5(G) R360.2 U136.6(QP2)
PWR_EN8: Q73.5(G) R362.2 U136.7(QP3)
PWR_EN9: Q82.5(G) R399.2 U144.4(QP0)
PWR_EN10: Q83.5(G) R401.2 U144.5(QP1)
PWR_EN11: Q84.5(G) R403.2 U144.6(QP2)
PWR_EN12: Q86.5(G) R406.2 U144.7(QP3)
PWR_EN13: Q87.5(G) R408.2 U145.4(QP0)
PWR_EN14: Q88.5(G) R410.2 U145.5(QP1)
PWR_EN15: Q89.5(G) R412.2 U145.6(QP2)
PWR_EN16: Q85.5(G) R397.2 U145.7(QP3)
PWR_SCL: R33.2 U1.L2(PWR_SCL_(FN0)) U16.16(SCL) ; also on sheet 9
PWR_SDA: R34.2 U1.L3(PWR_SDA_(FN0)) U16.17(SDA) ; also on sheet 9
PXTAL_IN: C11.1 R25.1 U1.R18(PXTAL_IN_(FN0)) Y1.3(OUT)
PXTAL_OUT: C10.1 R25.2 U1.T18(PXTAL_OUT_(FN0)) Y1.1(IN)
RST_AP#: C339.1 J7.15(SRST#) Q2.G Q12.D R35.2 SW5.1 SW5.3 U1.L1(RESET_IN#_(FN0))
SDI: R389.1 U133.15(SDI)
SLEEPn: R134.1 U16.22(SLEEPn)
SPI_CLK: U1.H4(MFP111(SSP2_CLK)_(FN4)) ; also on sheet 4
SPI_FRM: U1.H3(MFP112(SSP2_FRM)_(FN4)) ; also on sheet 4
SPI_NOR_ON: U1.G1(MFP110_(CS#_SPI_BOOT)) ; also on sheet 4
SPI_RXD: U1.G4(MFP107(SSP2_RXD)_(FN4)) ; also on sheet 4
SPI_TXD: U1.G3(MFP108(SSP2_TXD)_(FN4)) ; also on sheet 4
STR1: U135.6(RC7) U136.1(STR) U137.1(STR)
STR2: U143.6(RC7) U144.1(STR) U145.1(STR)
SW1: L11.2 U16.3(SW1_1) U16.6(SW1_2)
SW2: L12.2 U16.14(SW2)
SYS_EN: R308.2 U159.2(GP5)
UART2_CBUS0: R554.1 R557.1 U134.6(CBUS0) ; also on sheet 9
UART3_RTX: J35.31 U1.E3(MFP99(UART3_RTX)_(FN2/FN3)) U171.6(I/O6)
UART3_TRX: J35.33 U1.D2(MFP98(UART3_TRX)_(FN2/FN3)) U171.5(I/O5)
UART_USBDM: CM2.2(OUT1) R491.1 U134.1(USBDM)
UART_USBDP: CM2.1(IN1) R490.1 U134.12(USBDP)
USB_C_ID: J1.4(ID) U1.L17(USBC_ID_(FN0))
USB_C_VBUS: U1.P17(USBC_VBUS_DET_(FN0)) ; also on sheet 1
USB_CON_D+: CM1.3(OUT2) D12.2(CATHODE) J1.3(D+) R345.2
USB_CON_D-: CM1.4(IN2) D14.2(CATHODE) J1.2(D-) R102.2
USBC_DM: CM1.1(IN1) R102.1 U1.N18(USBC_D-_(FN0))
USBC_DP: CM1.2(OUT1) R345.1 U1.N17(USBC_D+_(FN0))
VCORE: R136.1 ; also on sheet 1 2
VOUT1: C193.1 C194.1 L11.1 R136.2 U16.10(FB1)
VOUT2: C195.2 L12.1 R115.1 U16.11(FB2)
VPICSW: C320.1 D32.3(A) J32.2(VDD) R309.1 R518.1 U159.1(VDD)
VPP_PIC1: J8.1(VPP) U135.1(RA3)
VPP_PIC2: J34.1(VPP) U143.1(RA3)
VR19_OTF: R109.1 R110.1 VR1.1(OTF)
VR19_PFM: R111.1 R112.1 VR1.2(PFM)
VR19_PGOOD: R70.1 R118.1 U16.9(EN1) VR1.8(PGOOD)
VR19_PSET: R114.1 VR1.12(PSET)
VR19_SDI: R116.2 VR1.10(SHDN/SDI)
VR19_SVIN: C184.1 R109.2 R111.2 R117.2 VR1.9(SVIN)
VR19_VSET: R113.1 VR1.11(VSET)
VSYS: C185.1 C189.2 C190.2 C191.2 C192.1 C321.1 C329.2 C331.1 C332.2 C333.2 C362.1 Q24.D R117.1 R120.2 R121.2 R122.2 R134.2 R383.1 R385.2 R387.2 R388.2 R393.2 R418.2 R425.1 U16.4(PVIN1_1) U16.5(PVIN1_2) U16.15(PVIN2) U132.5(VIN) U133.1(SVIN) U133.7(PVIN2) U133.20(VINLDO) U141.5(VIN) U147.5(VIN) U154.3(VIN) U177.5(VP) U178.5(VP) U179.5(VP) U180.5(VP) VR1.7(PVIN) ; also on sheet 2 7
VSYS_HIB: C327.1 Q64.D R118.2 ; also on sheet 3 9
VSYS_IN: D32.1(C1) Q24.S Q64.S Q121.S R337.1 R381.1 ; also on sheet 9
WLAN_IRQ: U1.F2(MFP105_(PWR_CTL_SD)) ; also on sheet 2
WLAN_PDn: U1.F1(MFP106_(PWR_CTL_USB)) ; also on sheet 2
WLAN_RESETn: U1.G2(MFP109_(GPI_GSENSOR_INT)_(FN0)) ; also on sheet 2
WLAN_SD0: U1.B13(MFP30(MMC4_DAT0)_(FN1)) ; also on sheet 2
WLAN_SD1: U1.A13(MFP31(MMC4_DAT1)_(FN1)) ; also on sheet 2
WLAN_SD2: U1.D12(MFP32(MMC4_DAT2)_(FN1)) ; also on sheet 2
WLAN_SD3: U1.B12(MFP33(MMC4_DAT3)_(FN1)) ; also on sheet 2
WLAN_SDCLK: U1.A14(MFP29(MMC4_CLK)_(FN1)) ; also on sheet 2
WLAN_SDCMD: U1.B14(MFP28(MMC4_CMD)_(FN1)) ; also on sheet 2
N31000602: R22.2 U1.C15(MFP20_(FN0))
N35039659: R23.2 U1.F4(MFP100_(FN0))
N40156337: R24.2 U1.D1(MFP101_(FN0))
N40457134: C181.1 L10.2 R119.1 VR1.5(FB)
N40457194: L10.1 VR1.6(SW)
N41772500: C196.2 R122.1 U16.21(SVIN)
N41911325: R120.1 VR1.3(EN)
N42148910: C211.2 Q12.G R77.1
N42756900: R196.2 U134.7(TXD)
N42788721: R424.2 U131.4(EN/~{EN})
N42788794: R425.2 U132.4(EN/~{EN})
N42789231: C321.2 Q24.G R308.1 R337.2
N42789715: C327.2 Q64.G R381.2 R382.1
N42792074: R385.1 U133.18(MODE1)
N42792088: R387.1 U133.17(SLEEPn)
N42792186: C330.2 L35.1 R390.2 U133.3(FB2)
N42792204: L35.2 U133.6(SW2)
N42792276: C328.2 U133.19(VLDO)
N42792288: R388.1 U133.14(SS_DONE)
N42795329: J7.13(TDO) R257.2
N42854894: LED13.1(A) R270.1
N42898321: Q118.D R393.1 U141.4(EN/~{EN})
N42943757: Q119.D R418.1 U147.4(EN/~{EN})
N43246894: R510.1 R511.1 U135.9(RB5)
N43247441: R512.1 R513.1 U143.9(RB5)
N43534101: Q121.G R547.2

Not connected (* = marked no-connect by the designer): D32 2(NC)*; J7 11(RTCK)*; J33 4(ID)*; U1 A3(MFP86_(CD)_(FN0))* B3(MFP87_(WP)_(FN0))* D3(MFP94(MMC2_CMD)_(FN1))* J1(MFP118)* K1(MFP119)* K2(MFP120)* K3(MFP121)* K4(MFP122_(USB_OC#)_(FN0))* M17(USBH_D+_(FN0))* M18(USBH_D-_(FN0))* N3(EXT_WAKEUP)*; U16 18(NC_4)* 19(NC_5)*; U133 8(NC8)* 9(NC9)* 10(NC10)* 13(NC13)*; U134 8(RTS)* 11(CTS)*; U136 9(QS1) 10(QS2); U137 9(QS1) 10(QS2); U144 9(QS1) 10(QS2); U145 9(QS1) 10(QS2); U171 7(I/O7) 8(I/O8); U173 3(I/O3) 4(I/O4) 5(I/O5); Y1 2(NC1)* 4(NC2)*

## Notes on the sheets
sheet 10
- System Power supplies
- Default to PFM mode
- Mode1:H Mode2:L Cout2=1.8V:1.8V
- SDI = low enable EN= high enable
- DDR3 1.5V
- WIFI & other 1.8V
- VCORE 1.0V
- SYSTEM 3.3V
- Connect two ground in one point at the (-) terminal
  of the output capacitors in layout.
- I2C linux address: 0x18
sheet 11
- ASPEN-DEBUG/SDIO/SSP/UART/MISC
- ECO: Uart connection fix
- Camera Power Down
- Check data in/out connection
- Short as possible
- ID = 100
- Notes:
  1. MFP110 is dedicated for SPI NOR FLASH BOOT purpose
  2. A_ISET: connect 6.04Kohm 1% resistor to ground
- SYSTEM CLOCK
- Do NOT remove Q29, Q30 until pre-program part used
- increased C211 for possible
  reset too short issue
sheet 12
- Mod: added D33 to enable microUSB only power
- ECO 1: U159 P3-4 swap
         ICSPCLK isolation
         programmer error fix D32
- Power Button
- While off - pressing will turn unit on
  while on - momentary press will let software shutdown
  while on - holding it for 4 second will force shut down
  when bat low during hibernate, shutdown
- Mod: changed to enable both mini and micro USB power bricks
- USE FFC 21039-0732 @mouser
- Silkscreen: USB OTG
- Note:
  1.Co-layout
  2. close to port
sheet 13
- Place Close to J35
  Top or bottom OK
  Pin swap OK
  U170/U171 on J35 odd numbered pin side
  U172/U173 on J35 even numbered pin side
  U158 close to pin 1/2 end
  minimize trace length
- ALT FUNC NAMES
- ALT FUNC NAMES
- SSP3_CLK
- CCIC D7
- MKIN4/OUT1
- SSP3_FRM
- CCIC D6
- MKIN5/OUT1
- SSP3_RXD
- CCIC D5
- MKIN6/OUT2
- SSP3_TXD
- CCIC D4
- MKIN0/OUT3
- EXT_I2c
  supports various voltages
- CCIC D3
- MKIN1
- MKOUT1
- CCIC D2
- MKIN7
- MKOUT2
- CCIC D1
- MKIN3
- MKOUT3
- CCIC D0
- DKIN4
- CCIC MK
- CCIC VS
- DKIN5
- CCIC PK
- CCIC HS
- DKIN7
- CCIC PD
- GPIO99
- GPIO98
- 1WIRE
- Place close to pin
  wide trace for V5P0FEXT
- Note: Need location Bottom Entry Conn from ID
- use guard traces
- I2C linux address: 0x70
- Revised 50 pin, tied to top 8 pins
sheet 14
- Debug and console connections
- Note: Need location from ID
- Note:
  1.Co-layout
  2. close to port
- Silkscreen: console uart
- match K1/K3/K4
- ECO 2: Disconnected GND
- ECO 3: Footprint odd-even swap
- JTAG (inside only)
- ECO : reduced cap size for faster rst_ap# Trise
sheet 15
- USE FFC 21039-0732 @mouser
- Place close to pin
  wide trace forV5P0FEXT
- ECO: programming fix
- ECO 4: 5V feed to PIC
- Use OC for INTR
- I2C linux address: 0x20
- Note: Need location from ID
- RB5 = Connector ID
- Drive OE low during programming
- PIN SWAP OK
sheet 16
- USE FFC 21039-0732 @mouser
- Place close to pin
  wide trace forV5P0FEXT
- ECO 4: 5V feed to PIC
- ECO: programming fix
- Use OC for INTR
- Any case, VCC=5V signal3.3V
- I2C linux address: 0x21
- RB5 = Connector ID
- PIN SWAP OK
